(* Logix 5000 project; controller V16_L55_Blank vendor 1 type 14 code 51 rev 16.2; software revision 16.04 *)

TASK MainTask (continuous, watchdog 500 ms) : MainProgram

MODULES
   Local : vendor 1 type 14 code 51 (ICP 0, rev 16.2)
      MVI69E_AFC : vendor 1 type 0 code 15 (ICP 1, rev 1.1, Output RPI 5 ms)
END_MODULES

TYPE AFCEComponents :   // High precision gas component analysis (only supported version 2.07.000)
STRUCT
   C1 : REAL;   // Methane
   N2 : REAL;   // Nitrogen
   CO2 : REAL;   // Carbon Dioxide
   C2 : REAL;   // Ethane
   C3 : REAL;   // Propane
   H20 : REAL;   // Water
   H2S : REAL;   // Hydrogen Sulphide
   H2 : REAL;   // Hydrogen
   CO : REAL;   // Carbon Monoxide
   O2 : REAL;   // Oxygen
   IC4 : REAL;   // Iso-butane
   NC4 : REAL;   // Normal Butane
   IC5 : REAL;   // Iso-pentane
   NC5 : REAL;   // Normal-pentane
   C6 : REAL;   // Hexane
   C7 : REAL;   // Heptane
   C8 : REAL;   // Octane
   C9 : REAL;   // Nonane
   C10 : REAL;   // Decane
   He : REAL;   // Helium
   Ar : REAL;   // Argon
   NeoC5 : REAL;   // Not Used
   UxUser1 : REAL;   // Not Used
   UyUser2 : REAL;   // Not Used
   UxUser3 : REAL;   // Not Used
   UyUser4 : REAL;   // Not Used
   UxUser5 : REAL;   // Not Used
   UyUser6 : REAL;   // Not Used
   UxUser7 : REAL;   // Not Used
   UyUser8 : REAL;   // Not Used
   UxUser9 : REAL;   // Not Used
   UyUser10 : REAL;   // Not Used
END_STRUCT
END_TYPE

TYPE AFCEExtended :
STRUCT
   Trigger : BOOL;
   Data : AFCEExtendedData;
END_STRUCT
END_TYPE

TYPE AFCEExtendedData :
STRUCT
   Raw : INT[64];
END_STRUCT
END_TYPE

TYPE AFCEFirmwareVersion :
STRUCT
   Major : SINT;   // Major Version number
   Minor : SINT;   // Minor Version number
   Revision : INT;   // Revision
END_STRUCT
END_TYPE

TYPE AFCEFlag :   // Flags contains status information updated by ladder and also trigger bits for clock update
STRUCT
   AFCStopped : BOOL;   // Indicates that the module has sent a new input block to be processed by ladder - UPDATED BY LADDER
   AFCInputSequenceNum : INT;   // Meter number (0 -15) associated to blocks 1-16. Used to update "Profile" (meter type and product group.) UPDATED BY LADDER
END_STRUCT
END_TYPE

TYPE AFCEMeterAnalysis :   // Meter analysis components. Allows the processor to update molar analysis for low precision and high precision streams.
STRUCT
   Trigger : BOOL;   // Set to 1 to Send Updated Component Data to the Module
   Stream : INT;   // Stream for Analysis. Select 0 for current active stream.
   Error : AFCEMeterAnalysisError;   // Analysis Error
   Components : AFCEComponents;   // High precision gas components (floating point per component). Only supported for firmware version 2.07.000 or later
END_STRUCT
END_TYPE

TYPE AFCEMeterAnalysisError :
STRUCT
   StreamOutOfRange : BOOL;   // Requested Stream Number Out of Range
   StreamNotConfigured : BOOL;   // Requested Stream Not Configured
END_STRUCT
END_TYPE

TYPE AFCEMeterArchiveFetchError :
STRUCT
   ArchiveSelectionInvalid : BOOL;   // Archive File Selection Invalid
   AgeOutsideSize : BOOL;   // Age Outside Configured File Size
   ArchiveNeverWritten : BOOL;   // Age OK but Archive Record Never Written (new or reconfigured meter)
   Reserverd1 : BOOL;
   Reserverd2 : BOOL;
   Reserverd3 : BOOL;
   Reserverd4 : BOOL;
   Reserverd5 : BOOL;
   Reserverd6 : BOOL;
   Reserverd7 : BOOL;
   Reserverd8 : BOOL;
   Reserverd9 : BOOL;
   Reserverd10 : BOOL;
   Reserverd11 : BOOL;
   Reserverd12 : BOOL;
   Reserverd13 : BOOL;
END_STRUCT
END_TYPE

TYPE AFCEMeterCalRequestActionType :
STRUCT
   ZeroShift : BOOL;   // Zero Shift
   SetZero : BOOL;   // Set Zero
   SetSpan : BOOL;   // Set Span
   SetMid1 : BOOL;   // Set Mid 1
   SetMid2 : BOOL;   // Set Mid 2
   SetMid3 : BOOL;   // Set Mid 3
END_STRUCT
END_TYPE

TYPE AFCEMeterCalRequestActionValue :
STRUCT
   ZeroShift : AFCEMeterCalRequestValue;   // Zero Shift
   SetZero : AFCEMeterCalRequestValue;   // Set Zero
   SetSpan : AFCEMeterCalRequestValue;   // Set Span
   SetMid1 : AFCEMeterCalRequestValue;   // Set Mid 1
   SetMid2 : AFCEMeterCalRequestValue;   // Set Mid 2
   SetMid3 : AFCEMeterCalRequestValue;   // Set Mid 3
END_STRUCT
END_TYPE

TYPE AFCEMeterCalRequestValue :
STRUCT
   Applied : REAL;   // Applied
   Measured : REAL;   // Measured
END_STRUCT
END_TYPE

TYPE AFCEMeterCalResponse :
STRUCT
   Trigger : BOOL;   // Send Error Code and Values to module to be recorded
   ErrorCode : SINT;   // Error Code to send. 0-4 allowed. 0=No error. 1-4=User defined.
   Value : AFCEMeterCalRequestValue;   // Value to Send
   Count : DINT;   // Number of calibration responses
END_STRUCT
END_TYPE

TYPE AFCEMeterControl :   // Enable/Disable Meter and Streams
STRUCT
   Meter : AFCEMeterControlMeter;   // Control the Meter
   Stream : AFCEMeterControlStream;   // Control the Meter Streams
   ResetAccumulators : AFCEMeterSignals;   // Resets for meter accumulators
END_STRUCT
END_TYPE

TYPE AFCEMeterControlMeter :   // Enable and Disable Meter
STRUCT
   Enable : BOOL;   // Enable the Meter
   Disable : BOOL;   // Disable the Meter
END_STRUCT
END_TYPE

TYPE AFCEMeterControlStream :
STRUCT
   Selected : SINT;   // Stream to Enable or Disable and/or make active.
   EnableSelected : BOOL;   // Enable the Selected Stream
   DisableSelected : BOOL;   // Disable the Selected Stream
   SetSelectedToActive : BOOL;   // Set Selected to Active Stream
END_STRUCT
END_TYPE

TYPE AFCEMeterDifferentialGas :   // Differential Gas Meter
STRUCT
   Control : AFCEMeterControl;   // Meter Control
   Status : AFCEMeterStatus;   // Meter Status
   ProcessVariables : AFCEMeterDifferentialGasProcess;   // Input process variables to be transferred to the module
   Analysis : AFCEMeterAnalysis;   // Molar Analysis data to be transferred to the module (only for gas products with online gas chromatograph applications)
   Alarm : AFCEMeterDifferentialGasAlarm;   // Meter Alarm status and control
   Archive : AFCEMeterDifferentialGasArchive;   // Archive
   Profile : AFCEMeterProfile;   // Module profile (meter type/product group) transfered from the module
   Calibration : AFCEMeterDifferentialGasCal;   // Calibration
   BackPlaneReturn : AFCEMeterDifferentialGasBackPlaneReturn;
END_STRUCT
END_TYPE

TYPE AFCEMeterDifferentialGasAlarm :   // Alarm Status and Control
STRUCT
   Control : AFCEMeterDifferentialGasAlarmControl;   // Alarm Control
END_STRUCT
END_TYPE

TYPE AFCEMeterDifferentialGasAlarmControl :   // Differential Gas Process Alarm Control
STRUCT
   DifferentialPressure : AFCEMeterProcessAlarm;   // Differential Pressure Alarms
   FlowRate : AFCEMeterProcessAlarm;   // Flow Rate
   Temperature : AFCEMeterProcessAlarm;   // Temperature Alarms
   Pressure : AFCEMeterProcessAlarm;   // Pressure Alarms
END_STRUCT
END_TYPE

TYPE AFCEMeterDifferentialGasArchive :   // Different Gas Archive
STRUCT
   Write : AFCEMeterDifferentialGasArchiveWrite;
   Fetch : AFCEMeterDifferentialGasArchiveFetch;
END_STRUCT
END_TYPE

TYPE AFCEMeterDifferentialGasArchiveDflt :   // Default Configuration
STRUCT
   ClosingTimestamp : DINT;
   CumulativeActiveStreams : INT;
   CurrentActiveStream : SINT;
   MeterStatus : SINT;
   FlowingPeriod : DINT;
   PeriodDuration : DINT;
   AccumulatorTotalizer : DINT;
   AccumulatorResidue : REAL;
   MeterAlarms : DINT;
   PrimaryInput : REAL;   // Either Differential Pressure or Flow Rate
   Temperature : REAL;
   Pressure : REAL;
   RelativeDensity : REAL;
   ReferenceCompressibility : REAL;
   FlowingCompressibility : REAL;
   Fpv : REAL;
   PressureExtension : REAL;
   CoefficientDischarge : REAL;
   ExpansionFactor : REAL;
   Cprime : REAL;
   MassNRAccumulatorCurrent : REAL;   // Non-resettable
   MassNRAccumulatorOpening : REAL;   // Non-resettable
   EnergyNRAccumulatorCurrent : REAL;   // Non-resettable
   EnergyNRAccumulatorOpening : REAL;   // Non-resettable
   NetNRAccumulatorCurrent : REAL;   // Non-resettable
   NetNRAccumulatorOpening : REAL;   // Non-resettable
   GrossNRAccumulatorCurrent : REAL;   // Non-resettable
   GrossNRAccumulatorOpening : REAL;   // Non-resettable
   MolarFractionComponent01_C1 : REAL;
   MolarFractionComponent02_N2 : REAL;
   MolarFractionComponent03_CO2 : REAL;
   MolarFractionComponent04_C2 : REAL;
   MolarFractionComponent05_C3 : REAL;
   MolarFractionComponent06_H2O : REAL;
   MolarFractionComponent07_H2S : REAL;
   MolarFractionComponent08_H2 : REAL;
   MolarFractionComponent09_CO : REAL;
   MolarFractionComponent10_O2 : REAL;
   MolarFractionComponent11_IC4 : REAL;
   MolarFractionComponent12_NC4 : REAL;
   MolarFractionComponent13_IC5 : REAL;
   MolarFractionComponent14_NC5 : REAL;
   MolarFractionComponent15_C6 : REAL;
   MolarFractionComponent16_C7 : REAL;
   MolarFractionComponent17_C8 : REAL;
   MolarFractionComponent18_C9 : REAL;
   MolarFractionComponent19_C10 : REAL;
   MolarFractionComponent20_He : REAL;
   MolarFractionComponent21_Ar : REAL;
   UserDefinedFlowAverage1 : REAL;
   UserDefinedFlowAverage2 : REAL;
   UserDefinedFlowAverage3 : REAL;
END_STRUCT
END_TYPE

TYPE AFCEMeterDifferentialGasArchiveFetch :
STRUCT
   Daily : AFCEMeterDifferentialGasArchiveFetchT;
   Hourly : AFCEMeterDifferentialGasArchiveFetchT;
END_STRUCT
END_TYPE

TYPE AFCEMeterDifferentialGasArchiveFetchT :   // Fetch Archive
STRUCT
   Trigger : BOOL;   // Trigger Archive Fetch
   Age : INT;   // Initial Archive. 0 = Current Archive
   Error : AFCEMeterArchiveFetchError;   // Archive Fetch Error
   Default : AFCEMeterDifferentialGasArchiveDflt;   // Default Archive
   Raw : INT[100];   // Raw Archive
END_STRUCT
END_TYPE

TYPE AFCEMeterDifferentialGasArchiveWrite :   // Write Archive
STRUCT
   Daily : BOOL;   // Set to 1 to write daily archive
   Hourly : BOOL;   // Set to 1 to write hourly archive
END_STRUCT
END_TYPE

TYPE AFCEMeterDifferentialGasBackPlaneReturn :   // Differential Gas Meter
STRUCT
   StandardDefault : AFCEMeterDifferentialGasStandardDataDflt;
   StandardRaw : INT[14];
   Extended : AFCEExtended;
END_STRUCT
END_TYPE

TYPE AFCEMeterDifferentialGasCal :   // Processor Mediated Calibration
STRUCT
   Request : AFCEMeterDifferentialGasCalRequest;   // Calibration Request from module
   Response : AFCEMeterCalResponse;   // Processor Response
END_STRUCT
END_TYPE

TYPE AFCEMeterDifferentialGasCalRequest :
STRUCT
   ProcessVariable : AFCEMeterDifferentialGasCalRequestProces;   // Process Variable
   ActionType : AFCEMeterCalRequestActionType;   // Action Type
   Value : AFCEMeterCalRequestActionValue;   // Value
   Count : DINT;   // Number of calibration requests
END_STRUCT
END_TYPE

TYPE AFCEMeterDifferentialGasCalRequestProces :
STRUCT
   DifferentialPressure : BOOL;   // Differential Pressure
   Temperature : BOOL;   // Temperature
   Pressure : BOOL;   // Pressure
END_STRUCT
END_TYPE

TYPE AFCEMeterDifferentialGasProcess :   // Differential Gas Process Variables
STRUCT
   DifferentialPressure : REAL;   // Differential pressure if Primary Input = Differential pressure
   FlowRate : REAL;   // Flow Rate if Primary Input = Flow Rate
   Temperature : REAL;   // Temperature
   Pressure : REAL;   // Static pressure
END_STRUCT
END_TYPE

TYPE AFCEMeterDifferentialGasStandardDataDflt :   // EAFC Backplane Return Standard Data
STRUCT
   Meter_Alarms : DINT;   // Meter alarms
   NR_Acc_Net_Totalizer : DINT;   // Non-resettable accumulator, net, totalizer (m3)
   NR_Acc_Net_Residue : REAL;   // Non-resettable accumulator, net, residue (m3)
   FlowRate_Net : REAL;   // Flow rate, net (m3/h)
   FlowRate_Gross : REAL;   // Flow rate, gross (m3/h)
   Ifpv : REAL;   // AGA 8, Supercompressibility, Fpv
   Cprime : REAL;   // C-prime
END_STRUCT
END_TYPE

TYPE AFCEMeterDifferentialLiqBackPlaneReturn :   // Differential Liquid Meter
STRUCT
   StandardDefault : AFCEMeterDifferentialLiqStandardDataDflt;
   StandardRaw : INT[14];
   Extended : AFCEExtended;
END_STRUCT
END_TYPE

TYPE AFCEMeterDifferentialLiqCal :   // Processor Mediated Calibration
STRUCT
   Request : AFCEMeterDifferentialLiqCalRequest;   // Calibration Request from module
   Response : AFCEMeterCalResponse;   // Processor Response
END_STRUCT
END_TYPE

TYPE AFCEMeterDifferentialLiqCalRequest :
STRUCT
   ProcessVariable : AFCEMeterDifferentialLiqCalRequestProces;   // Process Variable
   ActionType : AFCEMeterCalRequestActionType;   // Action Type
   Value : AFCEMeterCalRequestActionValue;   // Value
   Count : DINT;   // Number of calibration requests
END_STRUCT
END_TYPE

TYPE AFCEMeterDifferentialLiqCalRequestProces :
STRUCT
   DifferentialPressure : BOOL;   // Differential Pressure
   Temperature : BOOL;   // Temperature
   Pressure : BOOL;   // Pressure
   Density : BOOL;   // Density
   WaterContent : BOOL;   // Water Content
END_STRUCT
END_TYPE

TYPE AFCEMeterDifferentialLiqStandardDataDflt :   // EAFC Backplane Return Standard Data
STRUCT
   Meter_Alarms : DINT;   // Meter alarms
   NR_Acc_Net_Totalizer : DINT;   // Non-resettable accumulator, net, totalizer (m3)
   NR_Acc_Net_Residue : REAL;   // Non-resettable accumulator, net, residue (m3)
   FlowRate_Net : REAL;   // Flow rate, net (m3/h)
   NR_Acc_Gross_Totalizer : DINT;   // Non-resettable accumulator, gross, totalizer (m3)
   NR_Acc_GrossStandard_Totalizer : DINT;   // Non-resettable accumulator, gross standard, totalizer (m3)
   NR_Acc_Mass_Totalizer : DINT;   // Non-resettable accumulator, mass, totalizer (kg)
END_STRUCT
END_TYPE

TYPE AFCEMeterDifferentialLiquid :   // Differential Liquid Meter
STRUCT
   Control : AFCEMeterControl;   // Meter Control
   Status : AFCEMeterStatus;   // Meter Status
   ProcessVariables : AFCEMeterDifferentialLiquidProcess;   // Input process variables to be transferred to the module
   Analysis : AFCEMeterAnalysis;   // Molar Analysis data to be transferred to the module (only for gas products with online gas chromatograph applications)
   Alarm : AFCEMeterDifferentialLiquidAlarm;   // Meter Alarms
   Archive : AFCEMeterDifferentialLiquidArchive;   // Archive
   Profile : AFCEMeterProfile;   // Module profile (meter type/product group) transfered from the module
   Calibration : AFCEMeterDifferentialLiqCal;   // Calibration
   BackPlaneReturn : AFCEMeterDifferentialLiqBackPlaneReturn;
END_STRUCT
END_TYPE

TYPE AFCEMeterDifferentialLiquidAlarm :
STRUCT
   Control : AFCEMeterDifferentialLiquidAlarmControl;   // Alarm Control
END_STRUCT
END_TYPE

TYPE AFCEMeterDifferentialLiquidAlarmControl :   // Differential Liquid Process Alarms
STRUCT
   DifferentialPressure : AFCEMeterProcessAlarm;   // Differential Pressure Alarms
   FlowRate : AFCEMeterProcessAlarm;   // Flow Rate
   Temperature : AFCEMeterProcessAlarm;   // Temperature Alarms
   Pressure : AFCEMeterProcessAlarm;   // Pressure Alarms
   Density : AFCEMeterProcessAlarm;   // Density Alarms
   WaterPercent : AFCEMeterProcessAlarm;   // Differential Pressure Alarms
END_STRUCT
END_TYPE

TYPE AFCEMeterDifferentialLiquidArchive :   // Different Liquid Archive
STRUCT
   Write : AFCEMeterDifferentialLiquidArchiveWrite;
   Fetch : AFCEMeterDifferentialLiquidArchiveFetch;
END_STRUCT
END_TYPE

TYPE AFCEMeterDifferentialLiquidArchiveDflt :   // Default Configuration
STRUCT
   ClosingTimestamp : DINT;
   CumulativeActiveStreams : INT;
   CurrentActiveStream : SINT;
   MeterStatus : SINT;
   FlowingPeriod : DINT;
   PeriodDuration : DINT;
   AccumulatorTotalizer : DINT;
   AccumulatorResidue : REAL;
   MeterAlarms : DINT;
   PrimaryInput : REAL;   // Either Differential Pressure or Flow Rate
   Temperature : REAL;
   Pressure : REAL;
   Density : REAL;
   WaterContent : REAL;
   ReferenceDensity : REAL;
   Ctpl : REAL;
   AGA3DensityExtension : REAL;
   AGA3CoefficientDischarge : REAL;
   Available01 : INT;
   Available02 : INT;
   Cprime : REAL;
   MassNRAccumulatorCurrent : REAL;   // Non-resettable
   MassNRAccumulatorOpening : REAL;   // Non-resettable
   Available03 : INT;
   Available04 : INT;
   Available05 : INT;
   Available06 : INT;
   NetNRAccumulatorCurrent : REAL;   // Non-resettable
   NetNRAccumulatorOpening : REAL;   // Non-resettable
   GrossNRAccumulatorCurrent : REAL;   // Non-resettable
   GrossNRAccumulatorOpening : REAL;   // Non-resettable
   GrossStandardNRAccumulatorOpening : REAL;   // Non-resettable
   GrossStandardNRAccumulatorCurrent : REAL;   // Non-resettable
   WaterNRAccumulatorCurrent : REAL;   // Non-resettable
   WaterNRAccumulatorOpening : REAL;   // Non-resettable
   API2540VaporPressureAbs : REAL;   // Non-resettable
   Available07 : INT;
   Available08 : INT;
   UserSpecifiedFlowAverage1 : REAL;
   UserSpecifiedFlowAverage2 : REAL;
   UserSpecifiedFlowAverage3 : REAL;
END_STRUCT
END_TYPE

TYPE AFCEMeterDifferentialLiquidArchiveFetch :
STRUCT
   Daily : AFCEMeterDifferentialLiquidArchiveFetchT;
   Hourly : AFCEMeterDifferentialLiquidArchiveFetchT;
END_STRUCT
END_TYPE

TYPE AFCEMeterDifferentialLiquidArchiveFetchT :   // Fetch Archive
STRUCT
   Trigger : BOOL;   // Trigger Archive Fetch
   Age : INT;   // 0 = Current Archive
   Error : AFCEMeterArchiveFetchError;   // Archive Fetch Error
   Default : AFCEMeterDifferentialLiquidArchiveDflt;   // Default Archive
   Raw : INT[100];   // Raw Archive
END_STRUCT
END_TYPE

TYPE AFCEMeterDifferentialLiquidArchiveWrite :   // Write Archive
STRUCT
   Daily : BOOL;   // Set to 1 to write daily archive
   Hourly : BOOL;   // Set to 1 to write hourly archive
END_STRUCT
END_TYPE

TYPE AFCEMeterDifferentialLiquidProcess :   // Differential Liquid Process Variables
STRUCT
   DifferentialPressure : REAL;   // Differential pressure if Primary Input = Differential pressure
   FlowRate : REAL;   // Flow Rate if Primary Input = Flow Rate
   Temperature : REAL;   // Temperature
   Pressure : REAL;   // Static Pressure
   Density : REAL;   // Density
   WaterPercent : REAL;   // Water %
END_STRUCT
END_TYPE

TYPE AFCEMeterLinearGas :   // Linear Gas Meter
STRUCT
   Control : AFCEMeterControl;   // Meter Control
   Status : AFCEMeterStatus;   // Meter Status
   ProcessVariables : AFCEMeterLinearGasProcess;   // Input process variables to be transferred to the module
   Analysis : AFCEMeterAnalysis;   // Molar Analysis data to be transferred to the module (only for gas products with online gas chromatograph applications)
   Alarm : AFCEMeterLinearGasAlarm;   // Meter Alarms
   Archive : AFCEMeterLinearGasArchive;   // Archive
   Profile : AFCEMeterProfile;   // Module profile (meter type/product group) transfered from the module
   Calibration : AFCEMeterLinearGasCal;   // Calibration
   BackPlaneReturn : AFCEMeterLinearGasBackPlaneReturn;
END_STRUCT
END_TYPE

TYPE AFCEMeterLinearGasAlarm :
STRUCT
   Control : AFCEMeterLinearGasAlarmControl;   // Alarm Control
END_STRUCT
END_TYPE

TYPE AFCEMeterLinearGasAlarmControl :   // Linear Gas Process Alarms
STRUCT
   PulseFrequency : AFCEMeterProcessAlarm;   // Pulse Frequency Alarms
   Temperature : AFCEMeterProcessAlarm;   // Temperature Alarms
   Pressure : AFCEMeterProcessAlarm;   // Pressure Alarms
   MeterPulses : AFCEMeterProcessAlarmFidelity;   // Meter Pulses Alarms
END_STRUCT
END_TYPE

TYPE AFCEMeterLinearGasArchive :   // Linear Gas Archive
STRUCT
   Write : AFCEMeterLinearGasArchiveWrite;
   Fetch : AFCEMeterLinearGasArchiveFetch;
END_STRUCT
END_TYPE

TYPE AFCEMeterLinearGasArchiveDflt :   // Default Configuration
STRUCT
   ClosingTimestamp : DINT;
   CumulativeActiveStreams : INT;
   CurrentActiveStream : SINT;
   MeterStatus : SINT;
   FlowingPeriod : DINT;
   PeriodDuration : DINT;
   AccumulatorTotalizer : DINT;
   AccumulatorResidue : REAL;
   MeterAlarms : DINT;
   PulseFrequency : REAL;
   Temperature : REAL;
   Pressure : REAL;
   RelativeDensity : REAL;
   ReferenceCompressibility : REAL;
   FlowingCompressibility : REAL;
   Fpv : REAL;
   KFactor : REAL;
   MeterFactor : REAL;
   InputPulseCount : DINT;
   CurrentManPulseCount : DINT;
   MassNRAccumulatorCurrent : REAL;   // Non-resettable
   MassNRAccumulatorOpening : REAL;   // Non-resettable
   EnergyNRAccumulatorCurrent : REAL;   // Non-resettable
   EnergyNRAccumulatorOpening : REAL;   // Non-resettable
   NetNRAccumulatorCurrent : REAL;   // Non-resettable
   NetNRAccumulatorOpening : REAL;   // Non-resettable
   GrossNRAccumulatorCurrent : REAL;   // Non-resettable
   GrossNRAccumulatorOpening : REAL;   // Non-resettable
   MolarFractionComponent01_C1 : REAL;
   MolarFractionComponent02_N2 : REAL;
   MolarFractionComponent03_CO2 : REAL;
   MolarFractionComponent04_C2 : REAL;
   MolarFractionComponent05_C3 : REAL;
   MolarFractionComponent06_H2O : REAL;
   MolarFractionComponent07_H2S : REAL;
   MolarFractionComponent08_H2 : REAL;
   MolarFractionComponent09_CO : REAL;
   MolarFractionComponent10_O2 : REAL;
   MolarFractionComponent11_IC4 : REAL;
   MolarFractionComponent12_NC4 : REAL;
   MolarFractionComponent13_IC5 : REAL;
   MolarFractionComponent14_NC5 : REAL;
   MolarFractionComponent15_C6 : REAL;
   MolarFractionComponent16_C7 : REAL;
   MolarFractionComponent17_C8 : REAL;
   MolarFractionComponent18_C9 : REAL;
   MolarFractionComponent19_C10 : REAL;
   MolarFractionComponent20_He : REAL;
   MolarFractionComponent21_Ar : REAL;
   UserSpecifiedFlowAverage1 : REAL;
   UserSpecifiedFlowAverage2 : REAL;
   UserSpecifiedFlowAverage3 : REAL;
END_STRUCT
END_TYPE

TYPE AFCEMeterLinearGasArchiveFetch :
STRUCT
   Daily : AFCEMeterLinearGasArchiveFetchT;
   Hourly : AFCEMeterLinearGasArchiveFetchT;
END_STRUCT
END_TYPE

TYPE AFCEMeterLinearGasArchiveFetchT :   // Fetch Archive
STRUCT
   Trigger : BOOL;   // Trigger Archive Fetch
   Age : INT;   // 0 = Current Archive
   Error : AFCEMeterArchiveFetchError;   // Archive Fetch Error
   Default : AFCEMeterLinearGasArchiveDflt;   // Default Archive
   Raw : INT[100];   // Raw Archive
END_STRUCT
END_TYPE

TYPE AFCEMeterLinearGasArchiveWrite :   // Write Archive
STRUCT
   Daily : BOOL;   // Set to 1 to write daily archive
   Hourly : BOOL;   // Set to 1 to write hourly archive
END_STRUCT
END_TYPE

TYPE AFCEMeterLinearGasBackPlaneReturn :   // Linear Gas Meter
STRUCT
   StandardDefault : AFCEMeterLinearGasStandardDataDflt;
   StandardRaw : INT[14];
   Extended : AFCEExtended;
END_STRUCT
END_TYPE

TYPE AFCEMeterLinearGasCal :   // Processor Mediated Calibration
STRUCT
   Request : AFCEMeterLinearGasCalRequest;   // Calibration Request from module
   Response : AFCEMeterCalResponse;   // Processor Response
END_STRUCT
END_TYPE

TYPE AFCEMeterLinearGasCalRequest :
STRUCT
   ProcessVariable : AFCEMeterLinearGasCalRequestProces;   // Process Variable
   ActionType : AFCEMeterCalRequestActionType;   // Action Type
   Value : AFCEMeterCalRequestActionValue;   // Value
   Count : DINT;   // Number of calibration requests
END_STRUCT
END_TYPE

TYPE AFCEMeterLinearGasCalRequestProces :
STRUCT
   PulseFrequency : BOOL;   // Pulse Frequency
   Temperature : BOOL;   // Temperature
   Pressure : BOOL;   // Pressure
END_STRUCT
END_TYPE

TYPE AFCEMeterLinearGasProcess :   // Linear Gas Process Variables
STRUCT
   PulseFrequency : REAL;   // Pulse Frequency (Hz)
   Temperature : REAL;   // Temperature
   Pressure : REAL;   // Pressure
   MeterPulses : DINT;   // Pulse count
END_STRUCT
END_TYPE

TYPE AFCEMeterLinearGasStandardDataDflt :   // EAFC Backplane Return Standard Data
STRUCT
   Meter_Alarms : DINT;   // Meter alarms
   NR_Acc_Net_Totalizer : DINT;   // Non-resettable accumulator, net, totalizer (m3)
   NR_Acc_Net_Residue : REAL;   // Non-resettable accumulator, net, residue (m3)
   FlowRate_Net : REAL;   // Flow rate, net (m3/h)
   FlowRate_Gross : REAL;   // Flow rate, gross / indicated (m3/h)
   Ifpv : REAL;   // AGA 8, Supercompressibility, Fpv
   Cprime : REAL;   // C-prime
END_STRUCT
END_TYPE

TYPE AFCEMeterLinearLiqBackPlaneReturn :   // Linear Liquid Meter
STRUCT
   StandardDefault : AFCEMeterLinearLiquidStandardDataDflt;
   StandardRaw : INT[14];
   Extended : AFCEExtended;
END_STRUCT
END_TYPE

TYPE AFCEMeterLinearLiquid :   // Linear Liquid Meter
STRUCT
   Control : AFCEMeterControl;   // Meter Control
   Status : AFCEMeterStatus;   // Meter Status
   ProcessVariables : AFCEMeterLinearLiquidProcess;   // Input process variables to be transferred to the module
   Analysis : AFCEMeterAnalysis;   // Molar Analysis data to be transferred to the module (only for gas products with online gas chromatograph applications)
   Alarm : AFCEMeterLinearLiquidAlarm;   // Meter Alarms
   Archive : AFCEMeterLinearLiquidArchive;   // Archive
   Profile : AFCEMeterProfile;   // Module profile (meter type/product group) transfered from the module
   Calibration : AFCEMeterLinearLiquidCal;   // Calibration
   BackPlaneReturn : AFCEMeterLinearLiqBackPlaneReturn;
END_STRUCT
END_TYPE

TYPE AFCEMeterLinearLiquidAlarm :
STRUCT
   Control : AFCEMeterLinearLiquidAlarmControl;   // Alarm Control
END_STRUCT
END_TYPE

TYPE AFCEMeterLinearLiquidAlarmControl :   // Linear Liquid Process Alarms
STRUCT
   PulseFrequency : AFCEMeterProcessAlarm;   // Pulse Frequency Alarms
   Temperature : AFCEMeterProcessAlarm;   // Temperature Alarms
   Pressure : AFCEMeterProcessAlarm;   // Pressure Alarms
   Density : AFCEMeterProcessAlarm;   // Density Alarms
   WaterPercent : AFCEMeterProcessAlarm;   // Water Percent Alarms
   MeterPulses : AFCEMeterProcessAlarmFidelity;   // Meter Pulses Alarms
END_STRUCT
END_TYPE

TYPE AFCEMeterLinearLiquidArchive :   // Different Liquid Archive
STRUCT
   Write : AFCEMeterLinearLiquidArchiveWrite;
   Fetch : AFCEMeterLinearLiquidArchiveFetch;
END_STRUCT
END_TYPE

TYPE AFCEMeterLinearLiquidArchiveDflt :   // Default Configuration
STRUCT
   ClosingTimestamp : DINT;   // Closing Timestamp
   CumulativeActiveStreams : INT;
   CurrentActiveStream : SINT;
   MeterStatus : SINT;
   FlowingPeriod : DINT;
   PeriodDuration : DINT;
   AccumulatorTotalizer : DINT;
   AccumulatorResidue : REAL;
   MeterAlarms : DINT;
   PulseFrequency : REAL;
   Temperature : REAL;
   Pressure : REAL;
   Density : REAL;
   WaterContent : REAL;
   ReferenceDensity : REAL;
   Ctpl : REAL;
   KFactor : REAL;
   MeterFactor : REAL;
   InputPulseCount : DINT;
   ManPulseCountCurrent : DINT;
   MassNRAccumulatorCurrent : REAL;   // Non-resettable
   MassNRAccumulatorOpening : REAL;   // Non-resettable
   Available01 : INT;
   Available02 : INT;
   Available03 : INT;
   Available04 : INT;
   NetNRAccumulatorCurrent : REAL;   // Non-resettable
   NetNRAccumulatorOpening : REAL;   // Non-resettable
   GrossNRAccumulatorCurrent : REAL;   // Non-resettable
   GrossNRAccumulatorOpening : REAL;   // Non-resettable
   GrossStandardNRAccumulatorOpening : REAL;   // Non-resettable
   GrossStandardNRAccumulatorCurrent : REAL;   // Non-resettable
   WaterNRAccumulatorCurrent : REAL;   // Non-resettable
   WaterNRAccumulatorOpening : REAL;   // Non-resettable
   API2540VaporPressureAbsolute : REAL;   // Non-resettable
   Available05 : INT;
   Available06 : INT;
   UserSpecifiedFlowAverage1 : REAL;
   UserSpecifiedFlowAverage2 : REAL;
   UserSpecifiedFlowAverage3 : REAL;
END_STRUCT
END_TYPE

TYPE AFCEMeterLinearLiquidArchiveFetch :
STRUCT
   Daily : AFCEMeterLinearLiquidArchiveFetchT;
   Hourly : AFCEMeterLinearLiquidArchiveFetchT;
END_STRUCT
END_TYPE

TYPE AFCEMeterLinearLiquidArchiveFetchT :   // Fetch Archive
STRUCT
   Trigger : BOOL;   // Trigger Archive Fetch
   Age : INT;   // 0 = Current Archive
   Error : AFCEMeterArchiveFetchError;   // Archive Fetch Error
   Default : AFCEMeterLinearLiquidArchiveDflt;   // Default Archive
   Raw : INT[100];   // Raw Archive
END_STRUCT
END_TYPE

TYPE AFCEMeterLinearLiquidArchiveWrite :   // Write Archive
STRUCT
   Daily : BOOL;   // Set to 1 to write daily archive
   Hourly : BOOL;   // Set to 1 to write hourly archive
END_STRUCT
END_TYPE

TYPE AFCEMeterLinearLiquidCal :   // Processor Mediated Calibration
STRUCT
   Request : AFCEMeterLinearLiquidCalRequest;   // Calibration Request from module
   Response : AFCEMeterCalResponse;   // Processor Response
END_STRUCT
END_TYPE

TYPE AFCEMeterLinearLiquidCalRequest :
STRUCT
   ProcessVariable : AFCEMeterLinearLiquidCalRequestProces;   // Process Variable
   ActionType : AFCEMeterCalRequestActionType;   // Action Type
   Value : AFCEMeterCalRequestActionValue;   // Value
   Count : DINT;   // Number of calibration requests
END_STRUCT
END_TYPE

TYPE AFCEMeterLinearLiquidCalRequestProces :
STRUCT
   PulseFrequency : BOOL;   // Pulse Frequency
   Temperature : BOOL;   // Temperature
   Pressure : BOOL;   // Pressure
   Density : BOOL;   // Density
   WaterContent : BOOL;   // Water Content
END_STRUCT
END_TYPE

TYPE AFCEMeterLinearLiquidProcess :   // Linear Liquid Process Variables
STRUCT
   PulseFrequency : REAL;   // Pulse frequency (Hz)
   Temperature : REAL;   // Temperature
   Pressure : REAL;   // Pressure
   Density : REAL;   // Density
   WaterPercent : REAL;   // Water (%)
   MeterPulses : DINT;   // Meter pulses
END_STRUCT
END_TYPE

TYPE AFCEMeterLinearLiquidStandardDataDflt :   // EAFC Backplane Return Standard Data
STRUCT
   Meter_Alarms : DINT;   // Meter alarms
   NR_Acc_Net_Totalizer : DINT;   // Non-resettable accumulator, net, totalizer (m3)
   NR_Acc_Net_Residue : REAL;   // Non-resettable accumulator, net, residue (m3)
   FlowRate_Net : REAL;   // Flow rate, net (m3/h)
   NR_Acc_Gross_Totalizer : DINT;   // Non-resettable accumulator, gross / indicated, totalizer (m3)
   NR_Acc_GrossStandard_Totalizer : DINT;   // Non-resettable accumulator, gross standard, totalizer (m3)
   NR_Acc_Mass_Totalizer : DINT;   // Non-resettable accumulator, mass, totalizer (kg)
END_STRUCT
END_TYPE

TYPE AFCEMeterProcessAlarm :   // Process Alarms
STRUCT
   SetGeneralFail : BOOL;   // Set to indicate General Failure of the Transmitter
   StaleData : BOOL;   // Clear to Indicate new process input data
   SetLowThreshold : BOOL;   // Set to indicate Lower Range Limit Exceeded
   SetHighThreshold : BOOL;   // Set to indicate Upper Range Limit Exceeded
   SetAutoClearStaleData : BOOL;   // Set to automatically clear stale data
END_STRUCT
END_TYPE

TYPE AFCEMeterProcessAlarmFidelity :   // Process Alarms
STRUCT
   SetGeneralFail : BOOL;   // Set to indicate General Failure of the Transmitter
   StaleData : BOOL;   // Clear to Indicate new process input data
   Reserved : BOOL;   // Reserved
   SetPulseFidelityAlarm : BOOL;   // Set to indicate Pulse Fidelity Alarm
   SetAutoClearStaleData : BOOL;   // Set to automatically clear stale data
END_STRUCT
END_TYPE

TYPE AFCEMeterProfile :   // Meter configuration profile
STRUCT
   MeterType : BOOL;   // 0=Differential, 1=Linear
   ProductGroup : BOOL;   // 0=Gas, 1=Liquid
   PrimaryInput : BOOL;   // For differential, 0=Differential Pressure 1=Flow Rate. For Linear, 0=Pulse Count 1=Pulse Frequency
   AOIMismatch : BOOL;   // AOI Meter type does not match module for meter number
END_STRUCT
END_TYPE

TYPE AFCEMeterSignals :   // Meter trigger accumulator and archive resets
STRUCT
   ResetAccumulator1 : BOOL;   // Set to 1 to reset resettable accumulator 1
   ResetAccumulator2 : BOOL;   // Set to 1 to reset resettable accumulator 2
   ResetAccumulator3 : BOOL;   // Set to 1 to reset resettable accumulator 3
   ResetAccumulator4 : BOOL;   // Set to 1 to reset resettable accumulator 4
END_STRUCT
END_TYPE

TYPE AFCEMeterStatus :   // Status
STRUCT
   Meter : AFCEMeterStatusMeter;   // Meter Status
   Stream : AFCEMeterStatusStream;   // Stream Status
END_STRUCT
END_TYPE

TYPE AFCEMeterStatusMeter :   // Meter Status
STRUCT
   Enabled : BOOL;   // Meter Enable Status, 1=enabled
   EnableAlarm : BOOL;   // If set either: 1. The meter is not configured. 2. The event log is full, the action was not performed.
END_STRUCT
END_TYPE

TYPE AFCEMeterStatusStream :
STRUCT
   Active : INT;   // Current Active Stream
   Enabled : AFCEMeterStatusStreamEnabled;   // Enabled Streams
   Configured : AFCEMeterStatusStreamEnabled;   // Configured Streams
   EnableAlarm : AFCEMeterStatusStreamAlarm;   // Enable Alarms
END_STRUCT
END_TYPE

TYPE AFCEMeterStatusStreamAlarm :   // Stream Alarms
STRUCT
   StreamOutOfRange : BOOL;   // Requested Stream Number Out of Range
   StreamNotConfigured : BOOL;   // Requested Stream not Configured
   StreamNotEnabled : BOOL;   // Requested Stream not Enabled
   EventLogFull : BOOL;   // Event Log Full, Action not Performed
END_STRUCT
END_TYPE

TYPE AFCEMeterStatusStreamEnabled :   // Stream Status 1 = Enabled
STRUCT
   Stream1 : BOOL;
   Stream2 : BOOL;
   Stream3 : BOOL;
   Stream4 : BOOL;
   Stream5 : BOOL;
   Stream6 : BOOL;
   Stream7 : BOOL;
   Stream8 : BOOL;
   Stream9 : BOOL;
   Stream10 : BOOL;
   Stream11 : BOOL;
   Stream12 : BOOL;
   Stream13 : BOOL;
   Stream14 : BOOL;
   Stream15 : BOOL;
   Stream16 : BOOL;
END_STRUCT
END_TYPE

TYPE AFCEModbusGateway :   // Modbus Gateway
STRUCT
   Command : AFCEModbusGatewayCommand[10];   // Modbus gateway commands - contains setup and modbus data
END_STRUCT
END_TYPE

TYPE AFCEModbusGatewayCommand :   // Modbus Gateway Command
STRUCT
   Config : AFCEModbusGatewayConfig;   // Config data to be entered by the user.
   Trigger : BOOL;   // Trigger the Command, when cleared module has responded.
   Data : INT[200];   // Contains modbus data written to the module (write commands)
END_STRUCT
END_TYPE

TYPE AFCEModbusGatewayConfig :   // Modbus Ggateway Configuration
STRUCT
   Enable : BOOL;   // Set to 1 to enable modbus gateway command (0=disable)
   StartRegister : DINT;   // Start modbus address
   RegisterCount : INT;   // Word count (200 max)
   FunctionType : BOOL;   // 0 = read command, 1 = write command
   RegisterType : BOOL;   // 0 = holding register, 1 = input register
   SlaveType : BOOL;   // 0 = primary slave, 1 = virtual slave
END_STRUCT
END_TYPE

TYPE AFCEModbusMaster :   // Modbus Master. Port 3 must be configured as modbus master through AFC Manager to use this feature.
STRUCT
   Enable : BOOL;   // Enable the modbus master funcionality
   CommandIndex : INT;   // Selects which command index will be executed
   Command : AFCEModbusMasterCommand[10];   // Each command contains a specific modbus request to be sent out of the port
END_STRUCT
END_TYPE

TYPE AFCEModbusMasterCommand :   // Modbus Master Command
STRUCT
   Config : AFCEModbusMasterConfig;   // Modbus Master Configuration
   ErrorCode : INT;   // Error Code associated to Modbus Master Command
   Pending : BOOL;   // Pending Modbus Master Command - waiting for Modbus Response
   ReturnedTransactionID : DINT;   // Changes to Config.TransactionID value when response has returned.
   Data : INT[100];   // Read or Write Data
END_STRUCT
END_TYPE

TYPE AFCEModbusMasterConfig :   // Modbus master command settings
STRUCT
   Enable : BOOL;   // Set to 1 to enable command (0=disable)
   FunctionType : BOOL;   // Set to 1 to select write command (0=read command)
   RegisterBank : BOOL;   // Set to 1 to select input register (0=holding register)
   DataType : AFCEModbusMasterDataType;   // Select data type format
   SwapOption : AFCEModbusMasterSwap;   // Select byte and word swap (1 = swap, 0 = no swap)
   TypeSwap : INT;   // This value is calculated by ladder logic and must not be modified by user
   SlaveAddress : INT;   // Modbus slave address of remote device
   ModbusAddress : INT;   // Modbus data address on remote slave
   ElementCount : INT;   // Number of data elements (125 words)
   TransactionID : INT;   // Transaction ID. This value is returned to the ReturnedTransaction ID when the response has been received.
END_STRUCT
END_TYPE

TYPE AFCEModbusMasterDataType :   // Modbus master data type
STRUCT
   Bit : BOOL;   // bit type
   Word : BOOL;   // word type (16-bit)
   Long : BOOL;   // long integer (32-bit)
   LongRemote : BOOL;   // long integer (32-bit)
END_STRUCT
END_TYPE

TYPE AFCEModbusMasterSwap :   // Modbus master swap words/ swap bytes
STRUCT
   SwapWords : BOOL;   // Swap words
   SwapBytes : BOOL;   // Swap bytes
END_STRUCT
END_TYPE

TYPE AFCEModbusPassThru :   // AFC Modbus Pass-thru
STRUCT
   Enable : BOOL;   // Set to 1 to enable pass-thru functionality (requires AFC Manager setting)
   MessagePresent : BOOL;   // Message present in the response block
   GetMessage : BOOL;   // Get the pass-thru message. When the bit is cleared the message has been transferred to the PLC.
   FunctionBitWrite : BOOL;   // Function bit write
   OverflowError : BOOL;   // Overflow error flag
   ModbusAddress : INT;   // Destination modbus address
   RegisterCount : INT;   // Number of elements associated to command
   ReadDataWord : INT[125];   // Contains received data for word commands
   ReadDataBit : AFCEModbusPassThruBitData;   // Contains received data for bit commands
END_STRUCT
END_TYPE

TYPE AFCEModbusPassThruBitData :   // AFC Modbus Pass-thru Bit Data
STRUCT
   Data : BOOL[2016];   // Contains received data for bit commands
END_STRUCT
END_TYPE

TYPE AFCEModuleDef :   // Main user defined data type
STRUCT
   ModbusGateway : AFCEModbusGateway;   // Reads and write data between processor and module modbus table
   ModbusMaster : AFCEModbusMaster;   // Setup modbus master commands to be sent to remote slaves (through Port 3)
   ModbusPassThru : AFCEModbusPassThru;   // Modbus pass-thru data
   SiteStatus : AFCESiteStatus;   // Site status
   MeterAlarms : AFCESiteAlarms;   // Meter Alarms
   Prove : AFCEProve;   // Prover
   Wallclock : AFCEWallclock;   // Set clock and get clock information
   Firmware : AFCEFirmwareVersion;   // Firmware information
   Util : AFCEUtil;   // Used by ladder logic
END_STRUCT
END_TYPE

TYPE AFCENetwork :
STRUCT
   Read : BOOL;   // Trigger to read network parameters
   Write : BOOL;   // Trigger to write network parameters
   Config : AFCENetworkConfig;   // Network parameters
   Error : INT;   // 0 = OK, -1 = Timeout, -2 = Gateway Index Out of Range
   Util : AFCENetworkUTIL;   // Internal variables
END_STRUCT
END_TYPE

TYPE AFCENetworkConfig :
STRUCT
   GatewayIndex : DINT;
   Physical_Interface_IP : INT[4];
   Physical_Interface_Network_Prefix : SINT;
   Default_Gateway_IP : INT[4];   // The IP address of the gateway. Must be in the same network as the web interface, or null.
   Server1_Network_Prefix : SINT;   // The network prefix length (number of subnet mask bits) of the interface for server 1; a number between 0 and 32.
   Server1_MBAP_Port : DINT;   // The Modbus-TCP port for server 1; 502, or a number between 1024 and 65535.
   Server1_Listener_IP : INT[4];   // The IP address of the network interface for server 1.
END_STRUCT
END_TYPE

TYPE AFCENetworkUTIL :
STRUCT
   State : INT;
   Buffer : SINT[240];
   TimeoutTimer : TIMER;
   TimeoutState : INT;
END_STRUCT
END_TYPE

TYPE AFCEProve :   // Prove
STRUCT
   Process : AFCEProveProcess;   // Process Variables
   Signals : AFCEProveSignals;   // AFC Prove Signals (triggers the proving update)
   Config : AFCEProveConfig;   // AFC Prove Control (configuration settings)
   PulseCounts : AFCEProvePulseCount;   // Pulse counts to be updated at the end of the run/pass
   ConfigInput : AFCEProveInputConfig;   // AFC prover input configuration
   Status : AFCEProveStatus;   // AFC prover status
   ErrorCode : INT;   // Prove error code
   ProveControlsEcho : INT;   // AFC module Echos the state of the Prove Controls
   RequestedMeterEcho : INT;   // AFC module Echos the Meter number requested
   RequestedCurvePointEcho : INT;   // AFC module Echos the requested Curve Point
   RunResults : AFCEProveRunResults;   // Prove and run results
   ProveEnabled : BOOL;   // ON if prove is enabled. This flag is coped from inputbuffer[247]
END_STRUCT
END_TYPE

TYPE AFCEProveConfig :   // Controls (configuration settings) associated to the prover
STRUCT
   Enable : AFCEProveConfigEnable;   // Controls at enable
   Accept : AFCEProveConfigAccept;   // Controls at accept
END_STRUCT
END_TYPE

TYPE AFCEProveConfigAccept :   // Prove controls at accept. If auto-accept is selected must be available at enable
STRUCT
   RequestedInterpolationPoint : INT;   // Requested interpolation point (0 nearest)
   ApplyMFChangeAllStreams : BOOL;   // Apply change in meter factor to all streams
   ApplyMFChangeCurve : BOOL;   // Apply change in meter factor to all curve points
   ApplyNewMF : BOOL;   // CApply new meter factor
END_STRUCT
END_TYPE

TYPE AFCEProveConfigEnable :   // Prove controls at enable
STRUCT
   MeterNumber : INT;   // Meter number requested (1-16)
   AutoAcceptProve : BOOL;   // Auto-accept the prove
   AutoContinueProve : BOOL;   // Auto-continue the prove
END_STRUCT
END_TYPE

TYPE AFCEProveInputConfig :   // Prove input block results - prover configuration
STRUCT
   Type : INT;   // Prover type
   Options : INT;   // Prover options
   RunsPerProveTotal : INT;   // Total runs per prove
   RunsPerProveSelected : INT;   // Selected runs per prove
   MaxRunsBeforeAbort : INT;   // Max total runs before abort
   ShortPassesPerRun : INT;   // Short passes per run if bidir = 2 , else 0
END_STRUCT
END_TYPE

TYPE AFCEProvePhaseBitmap :   // AFC prove phase bitmap
STRUCT
   NotSelected : BOOL;   // Not selected
   Active : BOOL;   // Active, not counting
   CountingPast1stSwitch : BOOL;   // Counting past 1st switch for Udir and forward leg for Bdir)
   Past2ndSwitchFwdLeg : BOOL;   // Past 2nd switch forward leg (bidirectional only)
   Past1stSwithRetLeg : BOOL;   // Past 1st switch return leg (bidirectional only)
   RunComplete : BOOL;   // Run complete. past 2nd switch.
END_STRUCT
END_TYPE

TYPE AFCEProveProcess :   // Prove process output from processor to the module
STRUCT
   Sequencing : AFCEProveSequencing;   // Prover sequencing
   Temperature : REAL;   // Temperature for Single Probe provers. And Inlet Temperature for Dual Probe Provers.
   OutletTemperature : REAL;   // Outlet Temperature for Provers with Dual Probes.
   SwitchBarTemperature : REAL;   // Switch bar temperature
   Pressure : REAL;   // Pressure for Single Probe provers. And Inlet Pressure for Dual Probe Provers.
   OutletPressure : REAL;   // Outlet Pressure for Provers with Dual Probes.
   ProverDensity : REAL;   // Prover density
END_STRUCT
END_TYPE

TYPE AFCEProvePulseCount :   // Values to be supplied at the end of the pass/run
STRUCT
   Meter : DINT;   // Meter pulse count
   MasterMeter : DINT;   // Master meter pulse count
END_STRUCT
END_TYPE

TYPE AFCEProveRunResults :   // Run results of the prove. Copied from the module to the pocessor
STRUCT
   CountAttempted : INT;   // Run count attempted
   CountCompleted : INT;   // Run count completed
   CountSelected : INT;   // Run count selected
   RunsSelected : INT;   // Bit Mapped Runs selected for calculations from completed runs
   NewMeterFactor : REAL;   // New meter factor
   ChangeInMeterFactor : REAL;   // Change in meter factor
END_STRUCT
END_TYPE

TYPE AFCEProveSequencing :   // AFC prove sequencing tag for phase selection and ball positioning
STRUCT
   Phase : AFCEProvePhaseBitmap;   // AFC phase sequencing
   BallPositionReady : BOOL;   // Ball position: Ready (Udir & Bdir only; fwd leg Bdir)
   BallPositionSealed : BOOL;   // Ball position: Sealed (Udir & Bdir only; fwd leg Bdir)
   BallPositionReadyBwdLeg : BOOL;   // Ball position: Ready bwd leg (Bdir only)
   BallPositionSealedBwdLeg : BOOL;   // Ball position: Sealed bwd leg (Bdir only)
END_STRUCT
END_TYPE

TYPE AFCEProveSignals :   // Contains the proving signals that will trigger specific tasks from the module
STRUCT
   EnableProve : BOOL;   // Enables the prove
   AcceptProve : BOOL;   // Accepts the prove
   RejectProve : BOOL;   // Reject the prove
   RunStart : BOOL;   // Starts the run
   RunComplete : BOOL;   // Flags that the run is complete
   RunCancel : BOOL;   // Cancels the run
   RunDelete : BOOL;   // Deletes the run
   PassComplete : BOOL;   // Flag that the pass is complete
   PauseProve : BOOL;   // Pauses the Proving Process
   AbortProve : BOOL;   // Aborts the prove
END_STRUCT
END_TYPE

TYPE AFCEProveStatus :   // Status of the prove (returned from the module to the processor)
STRUCT
   ProveAccepted : BOOL;   // Prove was accepted
   MeterFactorApplied : BOOL;   // Meter factor was applied
   MFAppliedToCurve : BOOL;   // Meter factor was applied to all points in the curve
   MFAppliedToStreams : BOOL;   // Meter factor was applied to all streams
   ProveRejectedByCommand : BOOL;   // Prove was rejected by command
   ProveRejectedNoRuns : BOOL;   // Prove was rejected - empty prove (no runs)
   ProveRejectedDivideBy0 : BOOL;   // Prove was rejected - divide by 0
   ProveEnabled : BOOL;   // Prove is enabled
   ProvingRunInProgress : BOOL;   // Proving run is in progress
   ProveRejectedAbort : BOOL;   // Prove rejected: abort
   ProvePaused : BOOL;   // Prove is paused
   RunCancelled : BOOL;   // Run Is cancelled
   RunTimedOut : BOOL;   // Run timed out
END_STRUCT
END_TYPE

TYPE AFCESiteAlarms :   // Indicates if a meter has any alarms
STRUCT
   Meter1 : BOOL;   // Meter in alarm
   Meter2 : BOOL;   // Meter in alarm
   Meter3 : BOOL;   // Meter in alarm
   Meter4 : BOOL;   // Meter in alarm
   Meter5 : BOOL;   // Meter in alarm
   Meter6 : BOOL;   // Meter in alarm
   Meter7 : BOOL;   // Meter in alarm
   Meter8 : BOOL;   // Meter in alarm
   Meter9 : BOOL;   // Meter in alarm
   Meter10 : BOOL;   // Meter in alarm
   Meter11 : BOOL;   // Meter in alarm
   Meter12 : BOOL;   // Meter in alarm
   Meter13 : BOOL;   // Meter in alarm
   Meter14 : BOOL;   // Meter in alarm
   Meter15 : BOOL;   // Meter in alarm
   Meter16 : BOOL;   // Meter in alarm
END_STRUCT
END_TYPE

TYPE AFCESiteStatus :   // Site status bits - contains general information about the module - not meter specific
STRUCT
   AFCActive : BOOL;   // AFC active
   ChecksumAlarms : BOOL;   // Checkum alarm active
   Reserved2 : BOOL;
   Reserved3 : BOOL;
   PLCHalted : BOOL;   // PLC in program mode or missing
   CfgChanged : BOOL;   // Configuration changed
   Powerup : BOOL;   // Module powered up
   ColdStart : BOOL;   // Module performed cold start (BBRAM initialized)
   ModbusMasterPending : BOOL;   // Modbus Master Poll Pending
   ModbusMasterComplete : BOOL;   // Modbus Master Poll Complete
   ModbusPassThruPending : BOOL;   // Modbus Pass-thru Input Pending
   CalibrationRequest : BOOL;   // Calibration request from module
   ProverEnabled : BOOL;   // Prover Enabled
   Reserved13 : BOOL;
   Reserved14 : BOOL;
   Reserved15 : BOOL;
END_STRUCT
END_TYPE

TYPE AFCETime :   // AFC time format used for wallclock update.
STRUCT
   Year : DINT;   // Year
   Month : DINT;   // Month
   Day : DINT;   // Day
   Hour : DINT;   // Hour
   Minute : DINT;   // Minute
   second : DINT;   // Seconds
END_STRUCT
END_TYPE

TYPE AFCEUtil :   // Used for internal ladder logic usage. These values must not be changed by user application.
STRUCT
   Flags : AFCEFlag;   // Wallclock update commands
   CycleCounter : INT;   // Reflects current block ID calculated by ladder to be sent to the module
   Buffer : AFCEUtilBuffer;
   Block : AFCEUtilBlock;
END_STRUCT
END_TYPE

TYPE AFCEUtilBlock :
STRUCT
   ProcessInput : INT;
   InterruptPending : AFCEUtilBlockInterrupt;
   InterruptComplete : AFCEUtilBlockInterrupt;
   NonInterruptPending : AFCEUtilBlockNonInterrupt;
   NonInterruptComplete : AFCEUtilBlockNonInterrupt;
END_STRUCT
END_TYPE

TYPE AFCEUtilBlockInterrupt :
STRUCT
   Now : BOOL;
   ModbusGateway : DINT;
   EnableDisable : BOOL;
   Analysis : DINT;
END_STRUCT
END_TYPE

TYPE AFCEUtilBlockNonInterrupt :
STRUCT
   Now : BOOL;
   ModbusMasterCommand : BOOL;
   ModbusMasterResponse : BOOL;
   Archive : DINT;
   Prover : BOOL;
   PassThru : BOOL;
   Calibration : BOOL;
END_STRUCT
END_TYPE

TYPE AFCEUtilBuffer :   // Buffer
STRUCT
   Input : INT[248];   // Input buffer contains the complete block to be copied from the module
   Output : INT[247];   // Output buffer contains data the complete block to be copied to the module
   Process : INT[180];
   ArchiveDay : INT[98];
   ArchiveHour : INT[98];
   Prove : INT[26];
   Analysis : INT[198];
   MeterEnableDisable : INT[4];
   StreamEnable : INT[36];
   StreamDisable : INT[36];
   StreamSelect : INT[24];
   MeterSignals : INT[24];
   Calibration : INT[36];
END_STRUCT
END_TYPE

TYPE AFCEWallclock :
STRUCT
   GetAFCTime : BOOL;   // Get current AFC Time
   SetAFCTimeFromPLCTime : BOOL;   // Set AFC time from PLC time. Updates current AFC time
   EnableLocalDateTime : BOOL;   // Enable Local Date Time.
   AFCTime : AFCETime;   // Coordinated Universal Time. Updated by either getting or setting AFC time.
END_STRUCT
END_TYPE

ADD_ON_INSTRUCTION AOI69EAFC   (* revision 1.5, ExecutePrescan *)
// Add-On instruction for the MVI69E-AFC.
// Module Interface.
// Revision note:
// Made changes to the ModbusGatewayConfig UDT StartRegister Tag Data Type from INT to DINT.
// Help:
// Compatible with version 4.04 of MVI69E-AFC firmware or higher.
// v1.3: Option to choose LocalDateTime.
// v1.4: Changed Prescan FLL instruction length from 240 words to 180 for proccess inputs. This stopped mismatch issue
// v1.4: Changed COP instruction length from 240 words to 180 on rung 19 for procces inputs to output block. Modified ProfileBlockID INT to DINT.
// v1.5: Made changes to the ModbusGatewayConfig UDT StartRegister Tag Data Type from INT to DINT.
VAR_IN_OUT
   ConnectionInput : INT[248]; {required}
   ConnectionOutput : INT[247]; {required}
   AFC : AFCEModuleDef; {required}
        .UTIL.BUFFER.PROVE[12]   // Main user defined data type Buffer
END_VAR
VAR
   WallclockCurrentPLCTime : DINT[7];
   UTCTimeDelta : DINT;
   TimeZoneString : STRING;
   StoppedTimer : TIMER;
   ProverSignals : DINT;
   ProverPhase : DINT;
   ProverControls : DINT;
   ProveEnabled : BOOL;
   ProfileBlockID : DINT;
   ModbusMasterOutput : INT;
   CycleCounterPreviousStopped : INT;
   Offset1 : DINT;
   NotStoppedTimer : TIMER;
   ModbusPassThruOverflowError : BOOL;
   ModbusPassThruOutput : DINT;
   ModbusPassThruMessagePresent : BOOL;
   ModbusPassThruFunctionBitWrite : BOOL;
   ModbusMasterTransactionNumber : DINT;
   ModbusMasterReadWrite : BOOL;   // 0=Read 1=Write
   ModbusMasterPending : BOOL;
   ModbusMasterLongCount : DINT;
   ModbusGatewayReadWrite : BOOL;   // 0=Read, 1=Write
   ModbusGatewayOutput : DINT;
   ModbusGatewayIndexBitPosition : DINT;
   ModbusGatewayIndex : DINT;
   MJFAULTS : DINT[12];
   LocalHourChange : DINT;
   LatchStopped : BOOL;
   ForceReset : BOOL;
   AvoidBufferOverflowFault : DINT;   // Need this to prevent Overflow Minor Fault
   AFCTime : AFCETime;
END_VAR

ROUTINE Logic   (* ladder *)
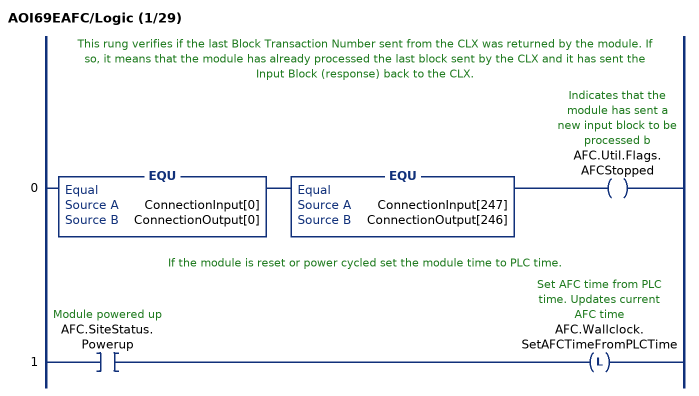
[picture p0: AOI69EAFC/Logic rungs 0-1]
   // This rung verifies if the last Block Transaction Number sent from the CLX was returned by the module. If so, it means that the module has already processed the last block sent by the CLX and it has sent the Input Block (response) back to the CLX.
   0: EQU(ConnectionInput[0],ConnectionOutput[0])EQU(ConnectionInput[247],ConnectionOutput[246])OTE(AFC.Util.Flags.AFCStopped);
   // If the module is reset or power cycled set the module time to PLC time.
   1: XIC(AFC.SiteStatus.Powerup)OTL(AFC.Wallclock.SetAFCTimeFromPLCTime);
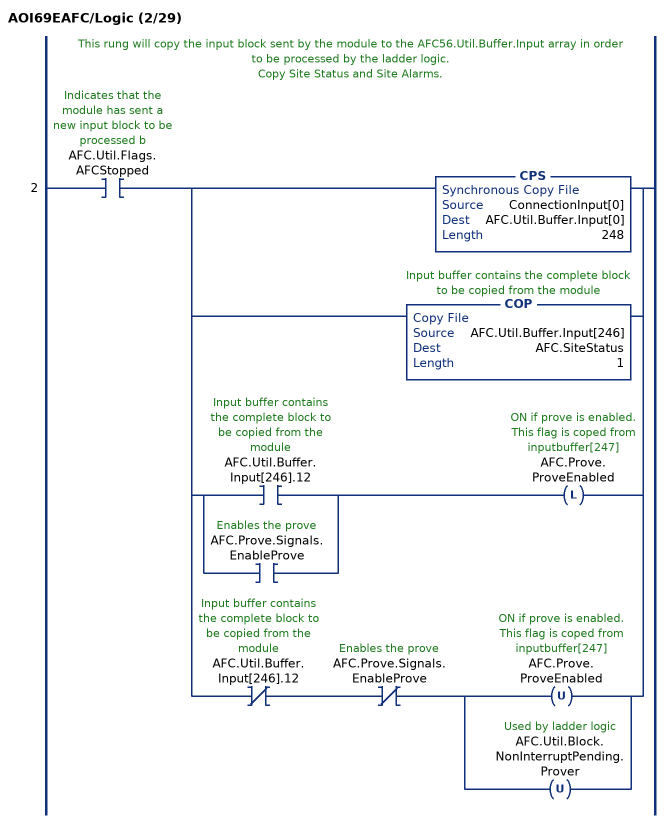
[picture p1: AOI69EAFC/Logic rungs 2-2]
   // This rung will copy the input block sent by the module to the AFC56.Util.Buffer.Input array in order to be processed by the ladder logic.
   // Copy Site Status and Site Alarms.
   2: XIC(AFC.Util.Flags.AFCStopped)[CPS(ConnectionInput[0],AFC.Util.Buffer.Input[0],248) ,COP(AFC.Util.Buffer.Input[246],AFC.SiteStatus,1) ,[XIC(AFC.Util.Buffer.Input[246].12) ,XIC(AFC.Prove.Signals.EnableProve) ] OTL(AFC.Prove.ProveEnabled) ,XIO(AFC.Util.Buffer.Input[246].12) XIO(AFC.Prove.Signals.EnableProve) [OTU(AFC.Prove.ProveEnabled) ,OTU(AFC.Util.Block.NonInterruptPending.Prover) ] ];
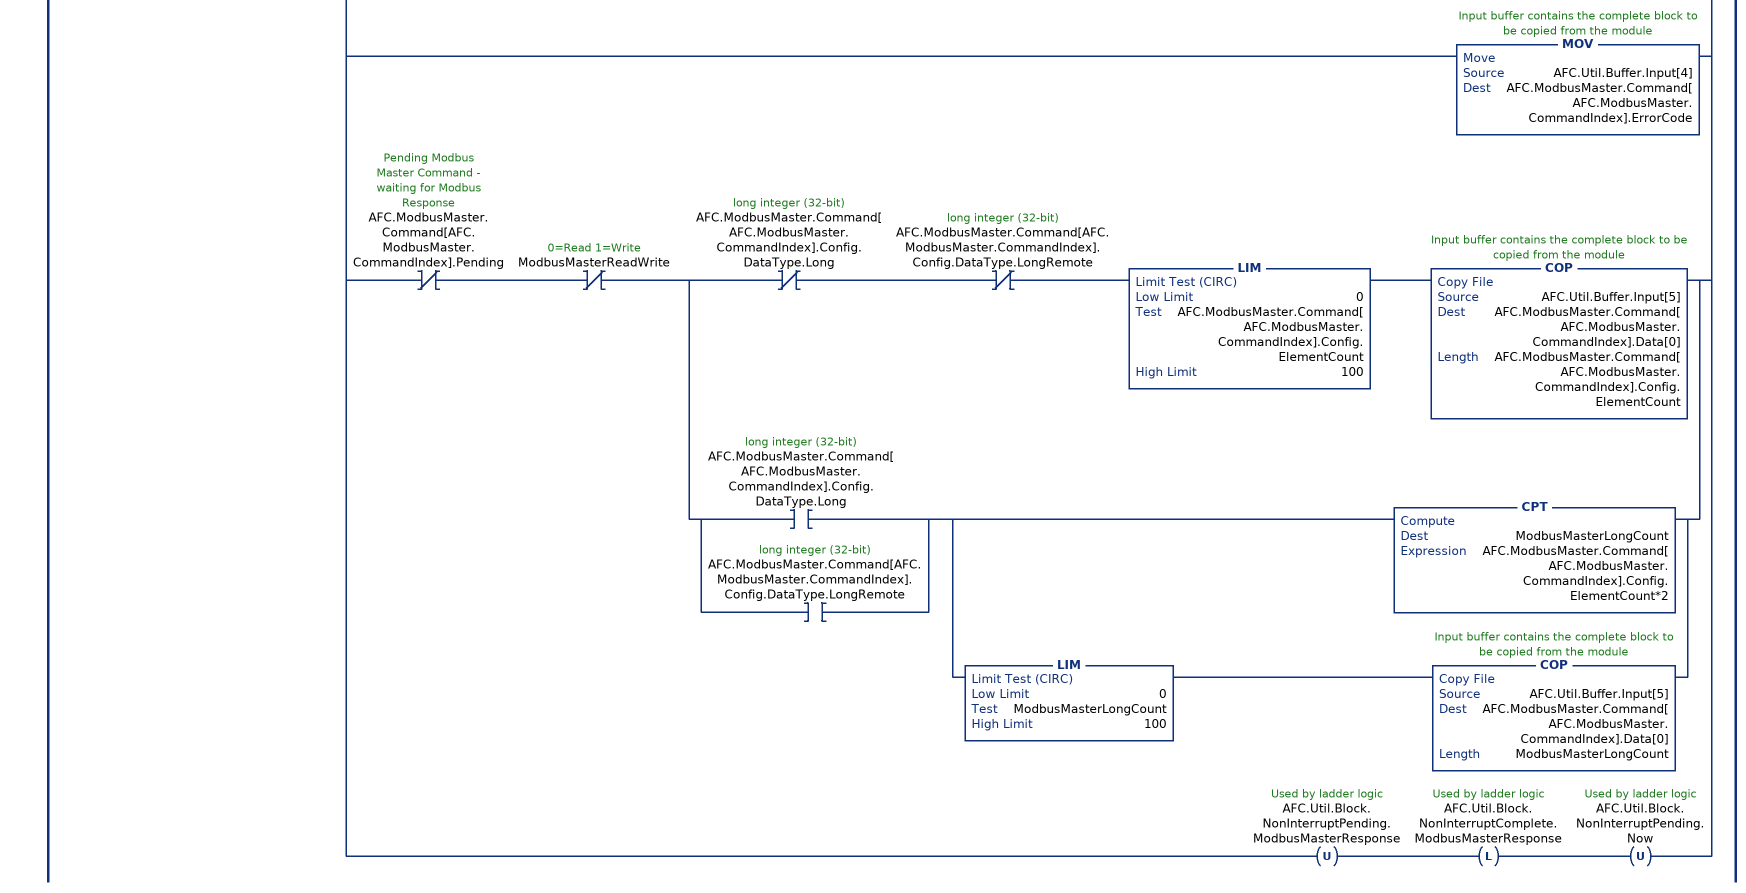
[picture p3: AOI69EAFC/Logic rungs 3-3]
   // Get Modbus Master data.
   3: XIC(AFC.Util.Flags.AFCStopped)XIC(AFC.ModbusMaster.Enable)LIM(0,AFC.ModbusMaster.CommandIndex,9)[EQU(AFC.Util.Buffer.Input[0],1000) [XIC(AFC.SiteStatus.ModbusMasterPending) OTL(AFC.ModbusMaster.Command[AFC.ModbusMaster.CommandIndex].Pending) ,XIO(AFC.SiteStatus.ModbusMasterPending) OTU(AFC.ModbusMaster.Command[AFC.ModbusMaster.CommandIndex].Pending) ,OTU(AFC.Util.Block.NonInterruptPending.ModbusMasterCommand) OTL(AFC.Util.Block.NonInterruptComplete.ModbusMasterCommand) OTU(AFC.Util.Block.NonInterruptPending.Now) ] ,EQU(AFC.Util.Buffer.Input[0],1001) [XIO(AFC.SiteStatus.ModbusMasterPending) OTU(AFC.ModbusMaster.Command[AFC.ModbusMaster.CommandIndex].Pending) ,MOV(AFC.Util.Buffer.Input[3],AFC.ModbusMaster.Command[AFC.ModbusMaster.CommandIndex].ReturnedTransactionID) ,MOV(AFC.Util.Buffer.Input[4],AFC.ModbusMaster.Command[AFC.ModbusMaster.CommandIndex].ErrorCode) ,XIO(AFC.ModbusMaster.Command[AFC.ModbusMaster.CommandIndex].Pending) XIO(ModbusMasterReadWrite) [XIO(AFC.ModbusMaster.Command[AFC.ModbusMaster.CommandIndex].Config.DataType.Long) XIO(AFC.ModbusMaster.Command[AFC.ModbusMaster.CommandIndex].Config.DataType.LongRemote) LIM(0,AFC.ModbusMaster.Command[AFC.ModbusMaster.CommandIndex].Config.ElementCount,100) COP(AFC.Util.Buffer.Input[5],AFC.ModbusMaster.Command[AFC.ModbusMaster.CommandIndex].Data[0],AFC.ModbusMaster.Command[AFC.ModbusMaster.CommandIndex].Config.ElementCount) ,[XIC(AFC.ModbusMaster.Command[AFC.ModbusMaster.CommandIndex].Config.DataType.Long) ,XIC(AFC.ModbusMaster.Command[AFC.ModbusMaster.CommandIndex].Config.DataType.LongRemote) ] [CPT(ModbusMasterLongCount,AFC.ModbusMaster.Command[AFC.ModbusMaster.CommandIndex].Config.ElementCount*2) ,LIM(0,ModbusMasterLongCount,100) COP(AFC.Util.Buffer.Input[5],AFC.ModbusMaster.Command[AFC.ModbusMaster.CommandIndex].Data[0],ModbusMasterLongCount) ] ] ,OTU(AFC.Util.Block.NonInterruptPending.ModbusMasterResponse) OTL(AFC.Util.Block.NonInterruptComplete.ModbusMasterResponse) OTU(AFC.Util.Block.NonInterruptPending.Now) ] ];
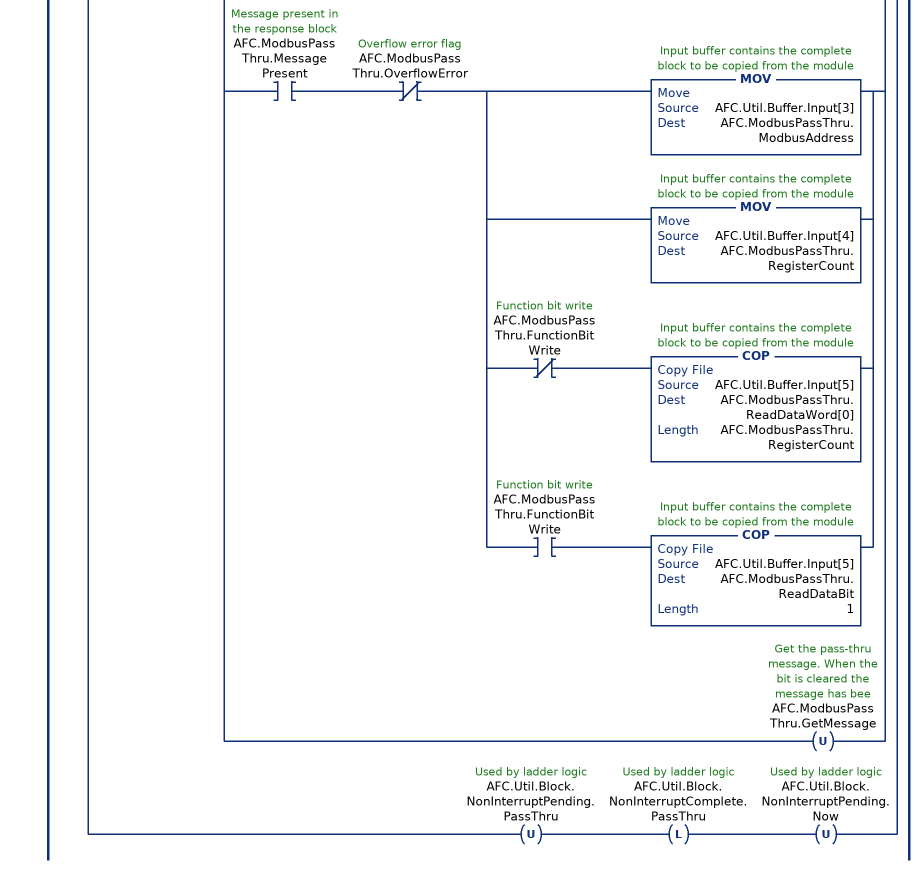
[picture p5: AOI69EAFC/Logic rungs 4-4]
   // Get Modbus Pass Thru data.
   4: XIC(AFC.Util.Flags.AFCStopped)EQU(AFC.Util.Buffer.Input[0],2000)XIC(AFC.ModbusPassThru.Enable)[XIC(AFC.ModbusPassThru.GetMessage) [[XIC(AFC.Util.Buffer.Input[2].0) OTL(AFC.ModbusPassThru.MessagePresent) ,XIO(AFC.Util.Buffer.Input[2].0) OTU(AFC.ModbusPassThru.MessagePresent) ,XIC(AFC.Util.Buffer.Input[2].1) OTL(AFC.ModbusPassThru.FunctionBitWrite) ,XIO(AFC.Util.Buffer.Input[2].1) OTU(AFC.ModbusPassThru.FunctionBitWrite) ,XIC(AFC.Util.Buffer.Input[3].2) OTL(AFC.ModbusPassThru.OverflowError) ,XIO(AFC.Util.Buffer.Input[3].2) OTU(AFC.ModbusPassThru.OverflowError) ] ,XIC(AFC.ModbusPassThru.MessagePresent) XIO(AFC.ModbusPassThru.OverflowError) [MOV(AFC.Util.Buffer.Input[3],AFC.ModbusPassThru.ModbusAddress) ,MOV(AFC.Util.Buffer.Input[4],AFC.ModbusPassThru.RegisterCount) ,XIO(AFC.ModbusPassThru.FunctionBitWrite) COP(AFC.Util.Buffer.Input[5],AFC.ModbusPassThru.ReadDataWord[0],AFC.ModbusPassThru.RegisterCount) ,XIC(AFC.ModbusPassThru.FunctionBitWrite) COP(AFC.Util.Buffer.Input[5],AFC.ModbusPassThru.ReadDataBit,1) ] ,OTU(AFC.ModbusPassThru.GetMessage) ] ,OTU(AFC.Util.Block.NonInterruptPending.PassThru) OTL(AFC.Util.Block.NonInterruptComplete.PassThru) OTU(AFC.Util.Block.NonInterruptPending.Now) ];
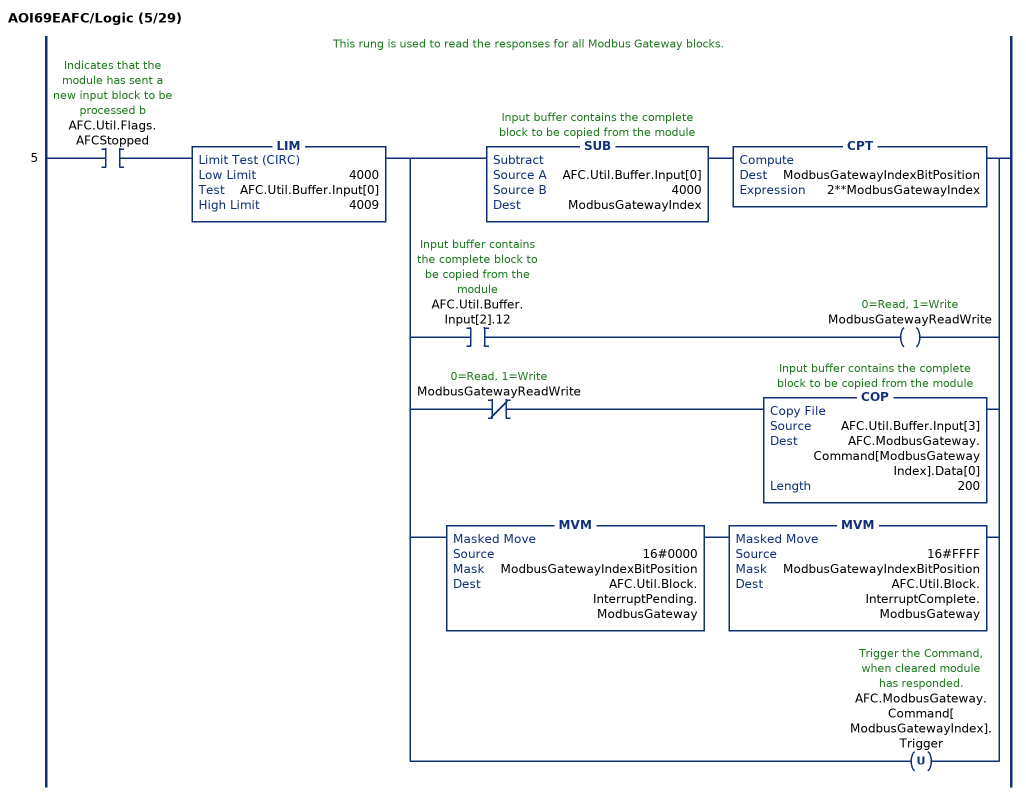
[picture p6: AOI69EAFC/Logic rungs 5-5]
   // This rung is used to read the responses for all Modbus Gateway blocks.
   5: XIC(AFC.Util.Flags.AFCStopped)LIM(4000,AFC.Util.Buffer.Input[0],4009)[SUB(AFC.Util.Buffer.Input[0],4000,ModbusGatewayIndex) CPT(ModbusGatewayIndexBitPosition,2**ModbusGatewayIndex) ,XIC(AFC.Util.Buffer.Input[2].12) OTE(ModbusGatewayReadWrite) ,XIO(ModbusGatewayReadWrite) COP(AFC.Util.Buffer.Input[3],AFC.ModbusGateway.Command[ModbusGatewayIndex].Data[0],200) ,MVM(16#0000,ModbusGatewayIndexBitPosition,AFC.Util.Block.InterruptPending.ModbusGateway) MVM(16#FFFF,ModbusGatewayIndexBitPosition,AFC.Util.Block.InterruptComplete.ModbusGateway) ,OTU(AFC.ModbusGateway.Command[ModbusGatewayIndex].Trigger) ];
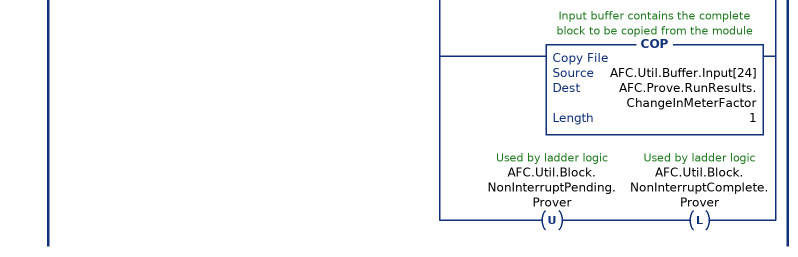
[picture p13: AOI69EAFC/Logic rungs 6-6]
   6: XIC(AFC.Util.Flags.AFCStopped)EQU(AFC.Util.Buffer.Input[0],5000)[XIC(ProverSignals.1) OTU(AFC.Prove.Signals.EnableProve) ,XIC(ProverSignals.2) OTU(AFC.Prove.Signals.AcceptProve) ,XIC(ProverSignals.3) OTU(AFC.Prove.Signals.RejectProve) ,XIC(ProverSignals.4) OTU(AFC.Prove.Signals.RunStart) ,XIC(ProverSignals.5) OTU(AFC.Prove.Signals.RunComplete) ,XIC(ProverSignals.6) OTU(AFC.Prove.Signals.RunCancel) ,XIC(ProverSignals.7) OTU(AFC.Prove.Signals.RunDelete) ,XIC(ProverSignals.9) OTU(AFC.Prove.Signals.PassComplete) ,XIC(ProverSignals.12) OTU(AFC.Prove.Signals.PauseProve) ,XIC(ProverSignals.14) OTU(AFC.Prove.Signals.AbortProve) ,MOV(AFC.Util.Buffer.Input[3],AFC.Prove.ConfigInput.Type) ,MOV(AFC.Util.Buffer.Input[4],AFC.Prove.ConfigInput.Options) ,MOV(AFC.Util.Buffer.Input[5],AFC.Prove.ConfigInput.RunsPerProveTotal) ,MOV(AFC.Util.Buffer.Input[6],AFC.Prove.ConfigInput.RunsPerProveSelected) ,MOV(AFC.Util.Buffer.Input[7],AFC.Prove.ConfigInput.MaxRunsBeforeAbort) ,MOV(AFC.Util.Buffer.Input[8],AFC.Prove.ConfigInput.ShortPassesPerRun) ,XIC(AFC.Util.Buffer.Input[12].0) OTL(AFC.Prove.Status.ProveAccepted) ,XIO(AFC.Util.Buffer.Input[12].0) OTU(AFC.Prove.Status.ProveAccepted) ,XIC(AFC.Util.Buffer.Input[12].1) OTL(AFC.Prove.Status.MeterFactorApplied) ,XIO(AFC.Util.Buffer.Input[12].1) OTU(AFC.Prove.Status.MeterFactorApplied) ,XIC(AFC.Util.Buffer.Input[12].2) OTL(AFC.Prove.Status.MFAppliedToCurve) ,XIO(AFC.Util.Buffer.Input[12].2) OTU(AFC.Prove.Status.MFAppliedToCurve) ,XIC(AFC.Util.Buffer.Input[12].3) OTL(AFC.Prove.Status.MFAppliedToStreams) ,XIO(AFC.Util.Buffer.Input[12].3) OTU(AFC.Prove.Status.MFAppliedToStreams) ,XIC(AFC.Util.Buffer.Input[12].4) OTL(AFC.Prove.Status.ProveRejectedByCommand) ,XIO(AFC.Util.Buffer.Input[12].4) OTU(AFC.Prove.Status.ProveRejectedByCommand) ,XIC(AFC.Util.Buffer.Input[12].5) OTL(AFC.Prove.Status.ProveRejectedNoRuns) ,XIO(AFC.Util.Buffer.Input[12].5) OTU(AFC.Prove.Status.ProveRejectedNoRuns) ,XIC(AFC.Util.Buffer.Input[12].6) OTL(AFC.Prove.Status.ProveRejectedDivideBy0) ,XIO(AFC.Util.Buffer.Input[12].6) OTU(AFC.Prove.Status.ProveRejectedDivideBy0) ,XIC(AFC.Util.Buffer.Input[12].8) OTL(AFC.Prove.Status.ProveEnabled) ,[XIO(AFC.Util.Buffer.Input[12].8) ,XIC(ProverSignals.2) ,XIC(ProverSignals.3) ,XIC(ProverSignals.14) ] OTU(AFC.Prove.Status.ProveEnabled) ,XIC(AFC.Util.Buffer.Input[12].9) OTL(AFC.Prove.Status.ProvingRunInProgress) ,XIO(AFC.Util.Buffer.Input[12].9) OTU(AFC.Prove.Status.ProvingRunInProgress) ,XIC(AFC.Util.Buffer.Input[12].10) OTL(AFC.Prove.Status.ProvePaused) ,XIO(AFC.Util.Buffer.Input[12].10) OTU(AFC.Prove.Status.ProvePaused) ,XIC(AFC.Util.Buffer.Input[12].11) OTL(AFC.Prove.Status.RunCancelled) ,XIO(AFC.Util.Buffer.Input[12].11) OTU(AFC.Prove.Status.RunCancelled) ,XIC(AFC.Util.Buffer.Input[12].12) OTL(AFC.Prove.Status.RunTimedOut) ,XIO(AFC.Util.Buffer.Input[12].12) OTU(AFC.Prove.Status.RunTimedOut) ,XIC(AFC.Util.Buffer.Input[12].14) OTL(AFC.Prove.Status.ProveRejectedAbort) ,XIO(AFC.Util.Buffer.Input[12].14) OTU(AFC.Prove.Status.ProveRejectedAbort) ,MOV(AFC.Util.Buffer.Input[13],AFC.Prove.ErrorCode) ,MOV(AFC.Util.Buffer.Input[14],AFC.Prove.ProveControlsEcho) ,MOV(AFC.Util.Buffer.Input[15],AFC.Prove.RequestedMeterEcho) ,MOV(AFC.Util.Buffer.Input[17],AFC.Prove.RequestedCurvePointEcho) ,COP(AFC.Util.Buffer.Input[18],AFC.Prove.RunResults.CountAttempted,1) ,COP(AFC.Util.Buffer.Input[19],AFC.Prove.RunResults.CountCompleted,1) ,MOV(AFC.Util.Buffer.Input[20],AFC.Prove.RunResults.CountSelected) ,MOV(AFC.Util.Buffer.Input[21],AFC.Prove.RunResults.RunsSelected) ,COP(AFC.Util.Buffer.Input[22],AFC.Prove.RunResults.NewMeterFactor,1) ,COP(AFC.Util.Buffer.Input[24],AFC.Prove.RunResults.ChangeInMeterFactor,1) ,OTU(AFC.Util.Block.NonInterruptPending.Prover) OTL(AFC.Util.Block.NonInterruptComplete.Prover) ];
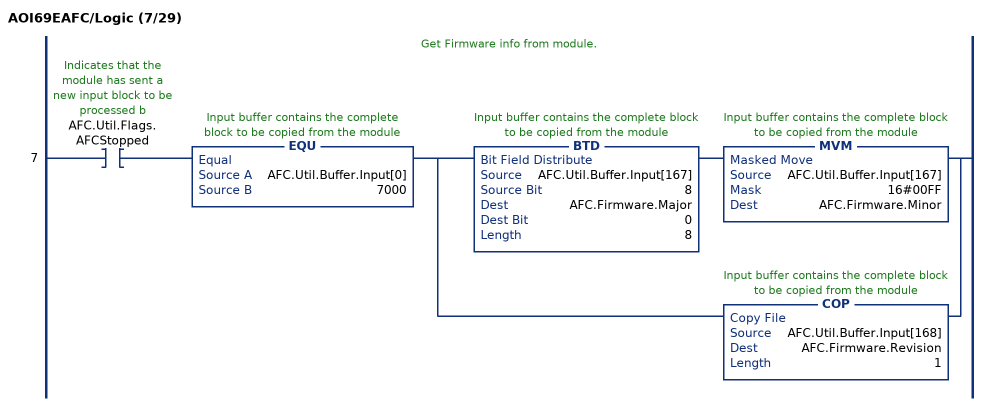
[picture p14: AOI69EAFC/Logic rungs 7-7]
   // Get Firmware info from module.
   7: XIC(AFC.Util.Flags.AFCStopped)EQU(AFC.Util.Buffer.Input[0],7000)[BTD(AFC.Util.Buffer.Input[167],8,AFC.Firmware.Major,0,8) MVM(AFC.Util.Buffer.Input[167],16#00FF,AFC.Firmware.Minor) ,COP(AFC.Util.Buffer.Input[168],AFC.Firmware.Revision,1) ];
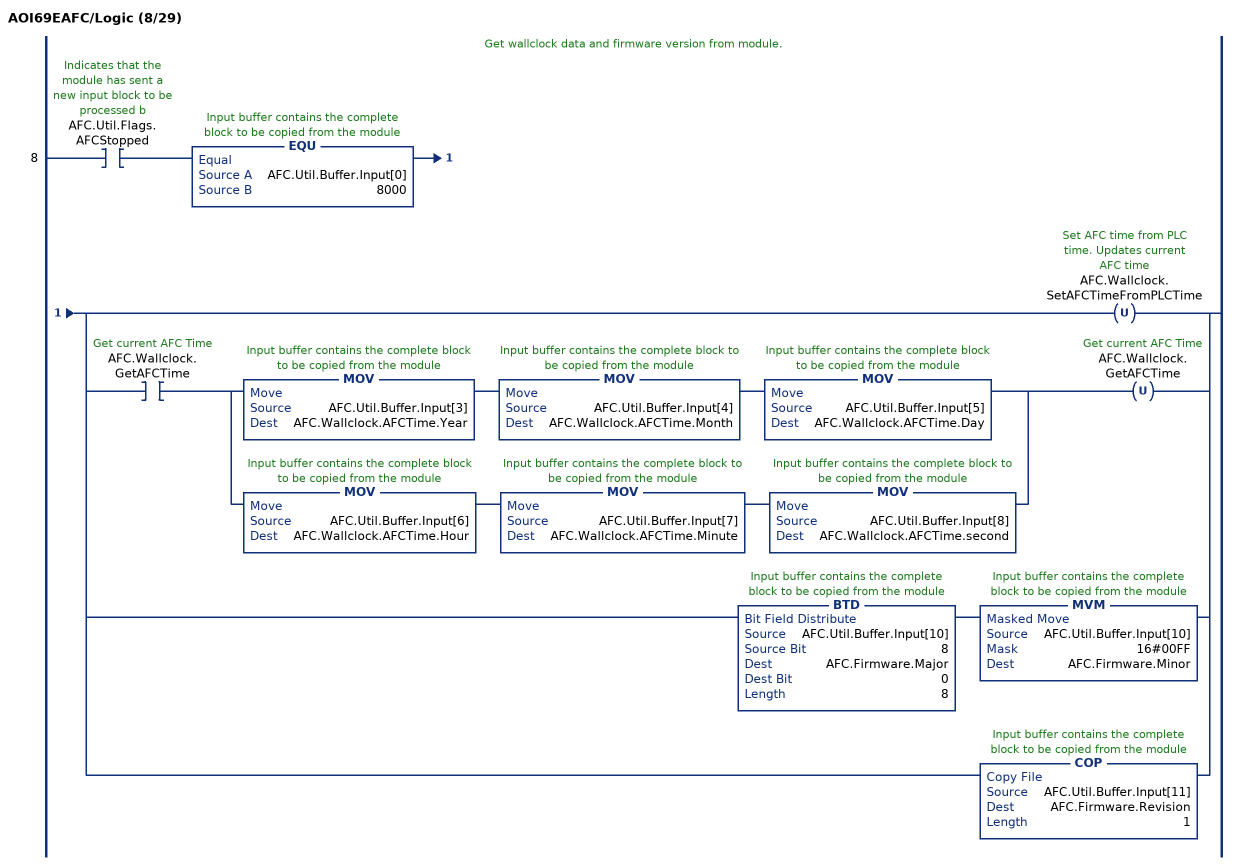
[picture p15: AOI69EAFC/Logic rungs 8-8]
   // Get wallclock data and firmware version from module.
   8: XIC(AFC.Util.Flags.AFCStopped)EQU(AFC.Util.Buffer.Input[0],8000)[OTU(AFC.Wallclock.SetAFCTimeFromPLCTime) ,XIC(AFC.Wallclock.GetAFCTime) [MOV(AFC.Util.Buffer.Input[3],AFC.Wallclock.AFCTime.Year) MOV(AFC.Util.Buffer.Input[4],AFC.Wallclock.AFCTime.Month) MOV(AFC.Util.Buffer.Input[5],AFC.Wallclock.AFCTime.Day) ,MOV(AFC.Util.Buffer.Input[6],AFC.Wallclock.AFCTime.Hour) MOV(AFC.Util.Buffer.Input[7],AFC.Wallclock.AFCTime.Minute) MOV(AFC.Util.Buffer.Input[8],AFC.Wallclock.AFCTime.second) ] OTU(AFC.Wallclock.GetAFCTime) ,[BTD(AFC.Util.Buffer.Input[10],8,AFC.Firmware.Major,0,8) MVM(AFC.Util.Buffer.Input[10],16#00FF,AFC.Firmware.Minor) ,COP(AFC.Util.Buffer.Input[11],AFC.Firmware.Revision,1) ] ];
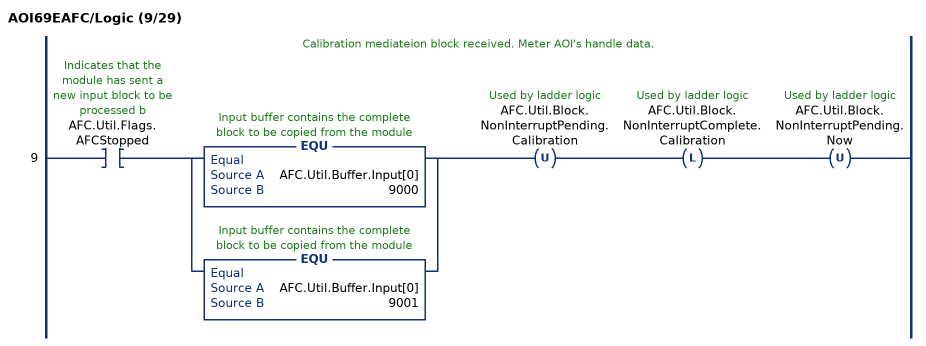
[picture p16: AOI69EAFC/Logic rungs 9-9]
   // Calibration mediateion block received. Meter AOI's handle data.
   9: XIC(AFC.Util.Flags.AFCStopped)[EQU(AFC.Util.Buffer.Input[0],9000) ,EQU(AFC.Util.Buffer.Input[0],9001) ]OTU(AFC.Util.Block.NonInterruptPending.Calibration)OTL(AFC.Util.Block.NonInterruptComplete.Calibration)OTU(AFC.Util.Block.NonInterruptPending.Now);
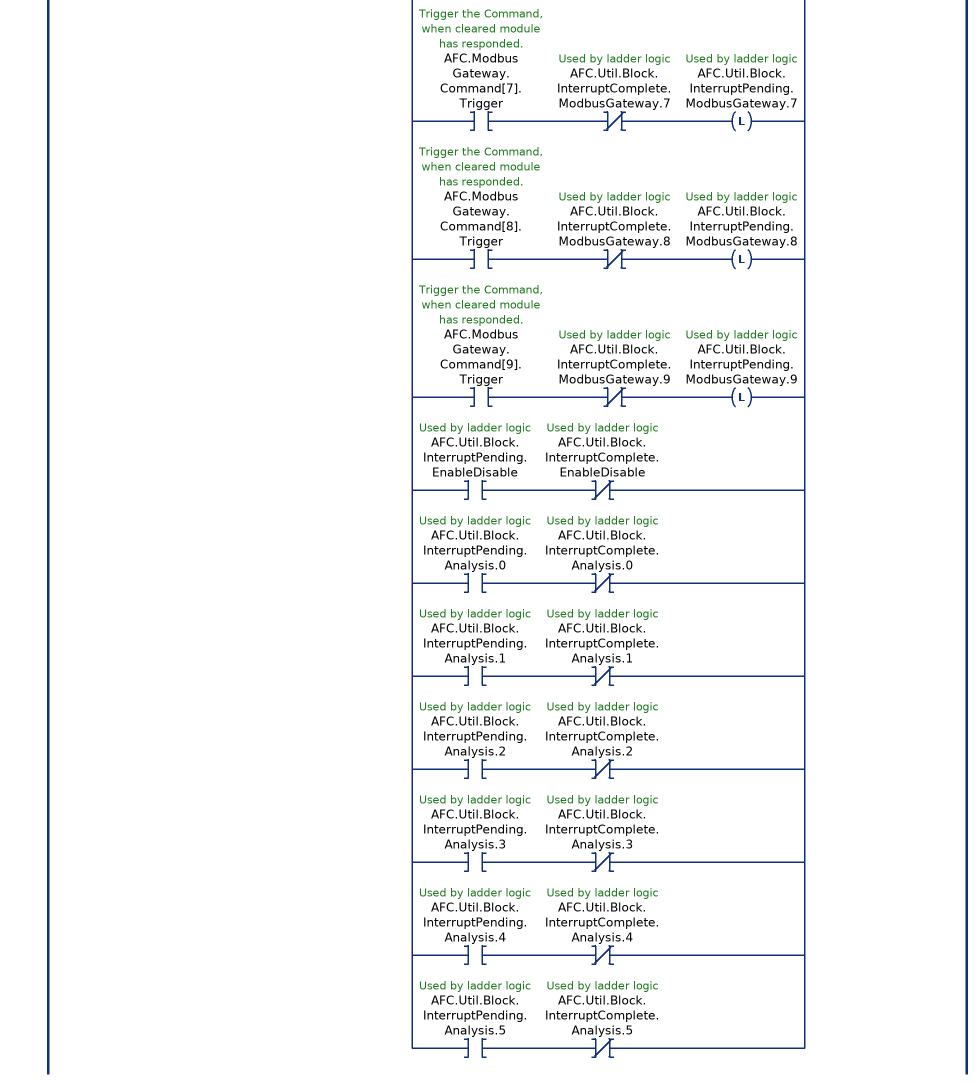
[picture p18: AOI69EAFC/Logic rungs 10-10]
   // Interrupt blocks (3000, 4000 and 7000) are interleaved between Process Input blocks.
   // Check if any interrupt block is pending.
   10: XIC(AFC.Util.Flags.AFCStopped)LIM(1,AFC.Util.Buffer.Input[0],11)[XIC(AFC.ModbusGateway.Command[0].Trigger) XIO(AFC.Util.Block.InterruptComplete.ModbusGateway.0) OTL(AFC.Util.Block.InterruptPending.ModbusGateway.0) ,XIC(AFC.ModbusGateway.Command[1].Trigger) XIO(AFC.Util.Block.InterruptComplete.ModbusGateway.1) OTL(AFC.Util.Block.InterruptPending.ModbusGateway.1) ,XIC(AFC.ModbusGateway.Command[2].Trigger) XIO(AFC.Util.Block.InterruptComplete.ModbusGateway.2) OTL(AFC.Util.Block.InterruptPending.ModbusGateway.2) ,XIC(AFC.ModbusGateway.Command[3].Trigger) XIO(AFC.Util.Block.InterruptComplete.ModbusGateway.3) OTL(AFC.Util.Block.InterruptPending.ModbusGateway.3) ,XIC(AFC.ModbusGateway.Command[4].Trigger) XIO(AFC.Util.Block.InterruptComplete.ModbusGateway.4) OTL(AFC.Util.Block.InterruptPending.ModbusGateway.4) ,XIC(AFC.ModbusGateway.Command[5].Trigger) XIO(AFC.Util.Block.InterruptComplete.ModbusGateway.5) OTL(AFC.Util.Block.InterruptPending.ModbusGateway.5) ,XIC(AFC.ModbusGateway.Command[6].Trigger) XIO(AFC.Util.Block.InterruptComplete.ModbusGateway.6) OTL(AFC.Util.Block.InterruptPending.ModbusGateway.6) ,XIC(AFC.ModbusGateway.Command[7].Trigger) XIO(AFC.Util.Block.InterruptComplete.ModbusGateway.7) OTL(AFC.Util.Block.InterruptPending.ModbusGateway.7) ,XIC(AFC.ModbusGateway.Command[8].Trigger) XIO(AFC.Util.Block.InterruptComplete.ModbusGateway.8) OTL(AFC.Util.Block.InterruptPending.ModbusGateway.8) ,XIC(AFC.ModbusGateway.Command[9].Trigger) XIO(AFC.Util.Block.InterruptComplete.ModbusGateway.9) OTL(AFC.Util.Block.InterruptPending.ModbusGateway.9) ,XIC(AFC.Util.Block.InterruptPending.EnableDisable) XIO(AFC.Util.Block.InterruptComplete.EnableDisable) ,XIC(AFC.Util.Block.InterruptPending.Analysis.0) XIO(AFC.Util.Block.InterruptComplete.Analysis.0) ,XIC(AFC.Util.Block.InterruptPending.Analysis.1) XIO(AFC.Util.Block.InterruptComplete.Analysis.1) ,XIC(AFC.Util.Block.InterruptPending.Analysis.2) XIO(AFC.Util.Block.InterruptComplete.Analysis.2) ,XIC(AFC.Util.Block.InterruptPending.Analysis.3) XIO(AFC.Util.Block.InterruptComplete.Analysis.3) ,XIC(AFC.Util.Block.InterruptPending.Analysis.4) XIO(AFC.Util.Block.InterruptComplete.Analysis.4) ,XIC(AFC.Util.Block.InterruptPending.Analysis.5) XIO(AFC.Util.Block.InterruptComplete.Analysis.5) ]OTL(AFC.Util.Block.InterruptPending.Now);
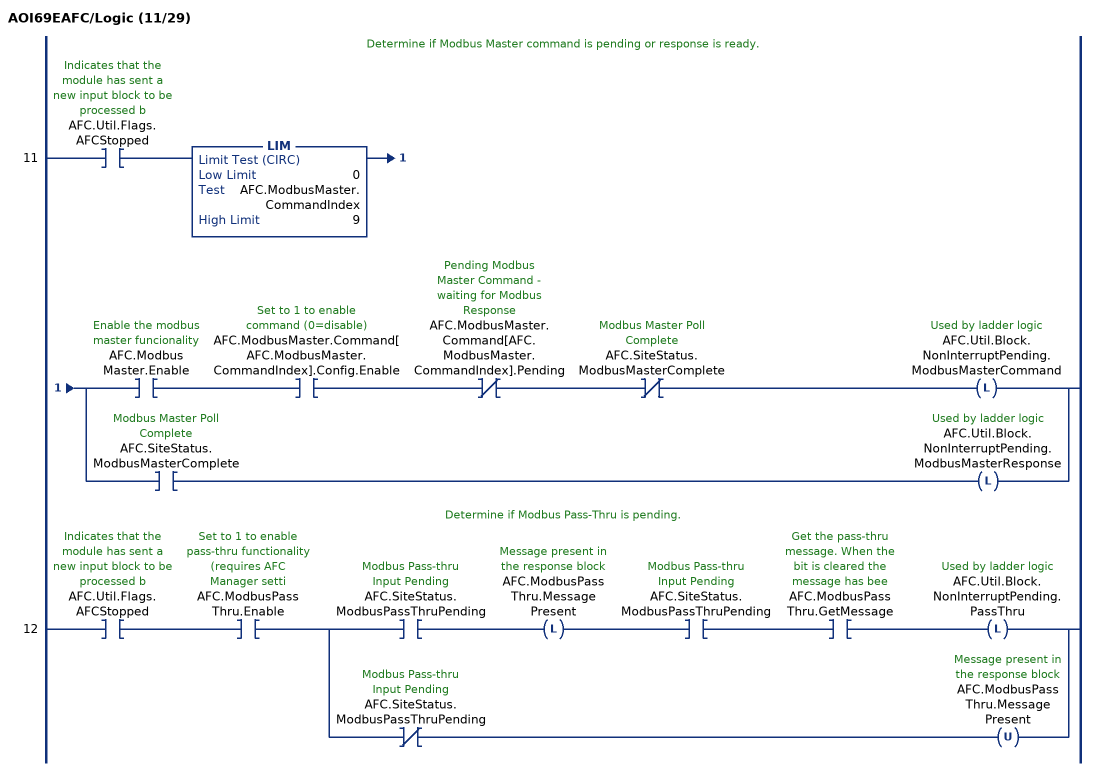
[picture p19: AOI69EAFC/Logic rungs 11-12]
   // Determine if Modbus Master command is pending or response is ready.
   11: XIC(AFC.Util.Flags.AFCStopped)LIM(0,AFC.ModbusMaster.CommandIndex,9)[XIC(AFC.ModbusMaster.Enable) XIC(AFC.ModbusMaster.Command[AFC.ModbusMaster.CommandIndex].Config.Enable) XIO(AFC.ModbusMaster.Command[AFC.ModbusMaster.CommandIndex].Pending) XIO(AFC.SiteStatus.ModbusMasterComplete) OTL(AFC.Util.Block.NonInterruptPending.ModbusMasterCommand) ,XIC(AFC.SiteStatus.ModbusMasterComplete) OTL(AFC.Util.Block.NonInterruptPending.ModbusMasterResponse) ];
   // Determine if Modbus Pass-Thru is pending.
   12: XIC(AFC.Util.Flags.AFCStopped)XIC(AFC.ModbusPassThru.Enable)[XIC(AFC.SiteStatus.ModbusPassThruPending) OTL(AFC.ModbusPassThru.MessagePresent) XIC(AFC.SiteStatus.ModbusPassThruPending) XIC(AFC.ModbusPassThru.GetMessage) OTL(AFC.Util.Block.NonInterruptPending.PassThru) ,XIO(AFC.SiteStatus.ModbusPassThruPending) OTU(AFC.ModbusPassThru.MessagePresent) ];
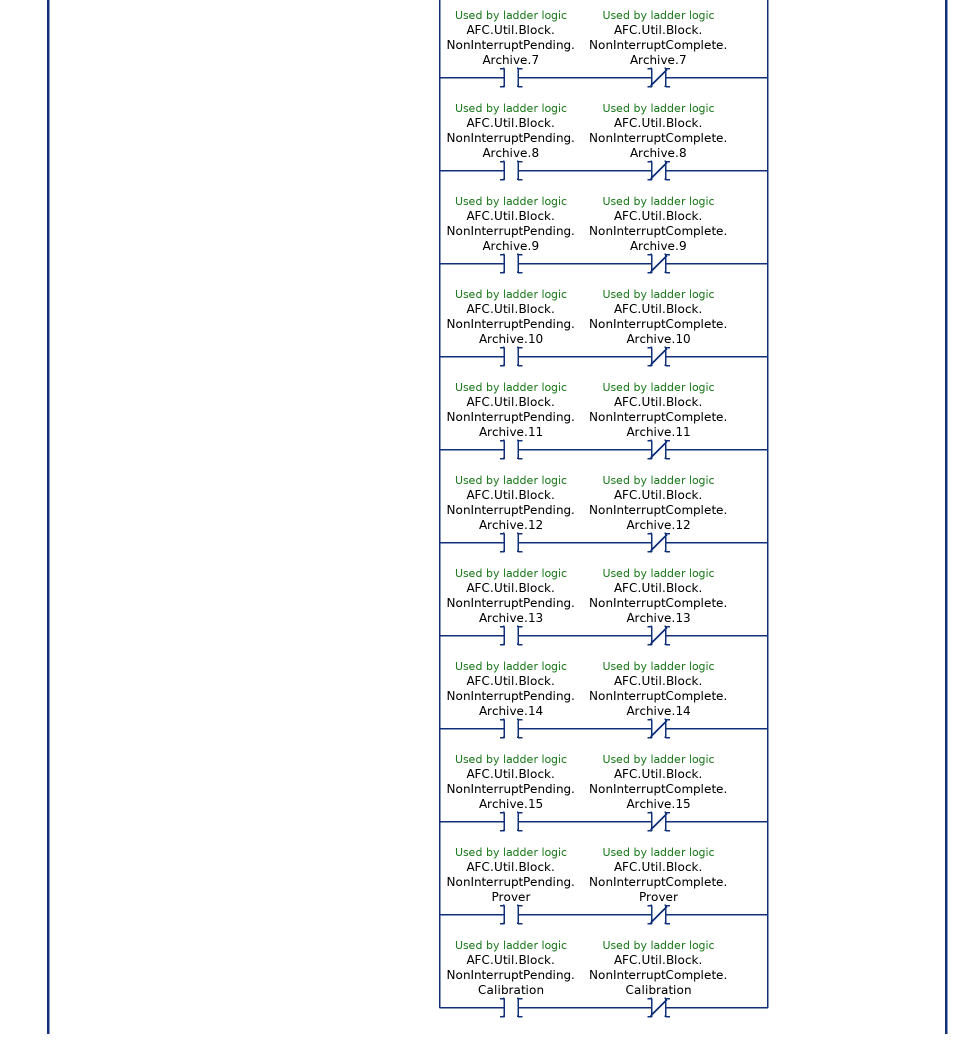
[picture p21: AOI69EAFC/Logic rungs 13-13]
   // Non-Interrupt blocks (1000, 2000 and 5000) occur after Process Input block 12.
   // Check if any non-interrupt block is pending.
   13: XIC(AFC.Util.Flags.AFCStopped)EQU(AFC.Util.Buffer.Input[0],12)[XIC(AFC.Util.Block.NonInterruptPending.ModbusMasterCommand) XIO(AFC.Util.Block.NonInterruptComplete.ModbusMasterCommand) ,XIC(AFC.Util.Block.NonInterruptPending.ModbusMasterResponse) XIO(AFC.Util.Block.NonInterruptComplete.ModbusMasterResponse) ,XIC(AFC.Util.Block.NonInterruptPending.PassThru) XIO(AFC.Util.Block.NonInterruptComplete.PassThru) ,XIC(AFC.Util.Block.NonInterruptPending.Archive.0) XIO(AFC.Util.Block.NonInterruptComplete.Archive.0) ,XIC(AFC.Util.Block.NonInterruptPending.Archive.1) XIO(AFC.Util.Block.NonInterruptComplete.Archive.1) ,XIC(AFC.Util.Block.NonInterruptPending.Archive.2) XIO(AFC.Util.Block.NonInterruptComplete.Archive.2) ,XIC(AFC.Util.Block.NonInterruptPending.Archive.3) XIO(AFC.Util.Block.NonInterruptComplete.Archive.3) ,XIC(AFC.Util.Block.NonInterruptPending.Archive.4) XIO(AFC.Util.Block.NonInterruptComplete.Archive.4) ,XIC(AFC.Util.Block.NonInterruptPending.Archive.5) XIO(AFC.Util.Block.NonInterruptComplete.Archive.5) ,XIC(AFC.Util.Block.NonInterruptPending.Archive.6) XIO(AFC.Util.Block.NonInterruptComplete.Archive.6) ,XIC(AFC.Util.Block.NonInterruptPending.Archive.7) XIO(AFC.Util.Block.NonInterruptComplete.Archive.7) ,XIC(AFC.Util.Block.NonInterruptPending.Archive.8) XIO(AFC.Util.Block.NonInterruptComplete.Archive.8) ,XIC(AFC.Util.Block.NonInterruptPending.Archive.9) XIO(AFC.Util.Block.NonInterruptComplete.Archive.9) ,XIC(AFC.Util.Block.NonInterruptPending.Archive.10) XIO(AFC.Util.Block.NonInterruptComplete.Archive.10) ,XIC(AFC.Util.Block.NonInterruptPending.Archive.11) XIO(AFC.Util.Block.NonInterruptComplete.Archive.11) ,XIC(AFC.Util.Block.NonInterruptPending.Archive.12) XIO(AFC.Util.Block.NonInterruptComplete.Archive.12) ,XIC(AFC.Util.Block.NonInterruptPending.Archive.13) XIO(AFC.Util.Block.NonInterruptComplete.Archive.13) ,XIC(AFC.Util.Block.NonInterruptPending.Archive.14) XIO(AFC.Util.Block.NonInterruptComplete.Archive.14) ,XIC(AFC.Util.Block.NonInterruptPending.Archive.15) XIO(AFC.Util.Block.NonInterruptComplete.Archive.15) ,XIC(AFC.Util.Block.NonInterruptPending.Prover) XIO(AFC.Util.Block.NonInterruptComplete.Prover) ,XIC(AFC.Util.Block.NonInterruptPending.Calibration) XIO(AFC.Util.Block.NonInterruptComplete.Calibration) ]OTL(AFC.Util.Block.NonInterruptPending.Now);
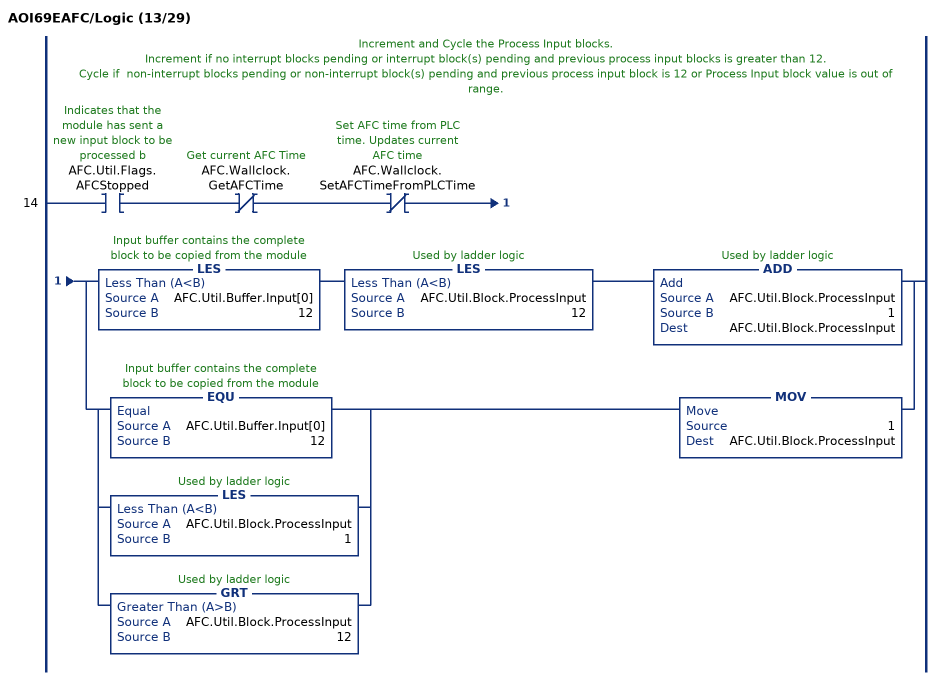
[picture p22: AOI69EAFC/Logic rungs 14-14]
   // Increment and Cycle the Process Input blocks.
   // Increment if no interrupt blocks pending or interrupt block(s) pending and previous process input blocks is greater than 12.
   // Cycle if  non-interrupt blocks pending or non-interrupt block(s) pending and previous process input block is 12 or Process Input block value is out of range.
   14: XIC(AFC.Util.Flags.AFCStopped)XIO(AFC.Wallclock.GetAFCTime)XIO(AFC.Wallclock.SetAFCTimeFromPLCTime)[LES(AFC.Util.Buffer.Input[0],12) LES(AFC.Util.Block.ProcessInput,12) ADD(AFC.Util.Block.ProcessInput,1,AFC.Util.Block.ProcessInput) ,[EQU(AFC.Util.Buffer.Input[0],12) ,LES(AFC.Util.Block.ProcessInput,1) ,GRT(AFC.Util.Block.ProcessInput,12) ] MOV(1,AFC.Util.Block.ProcessInput) ];
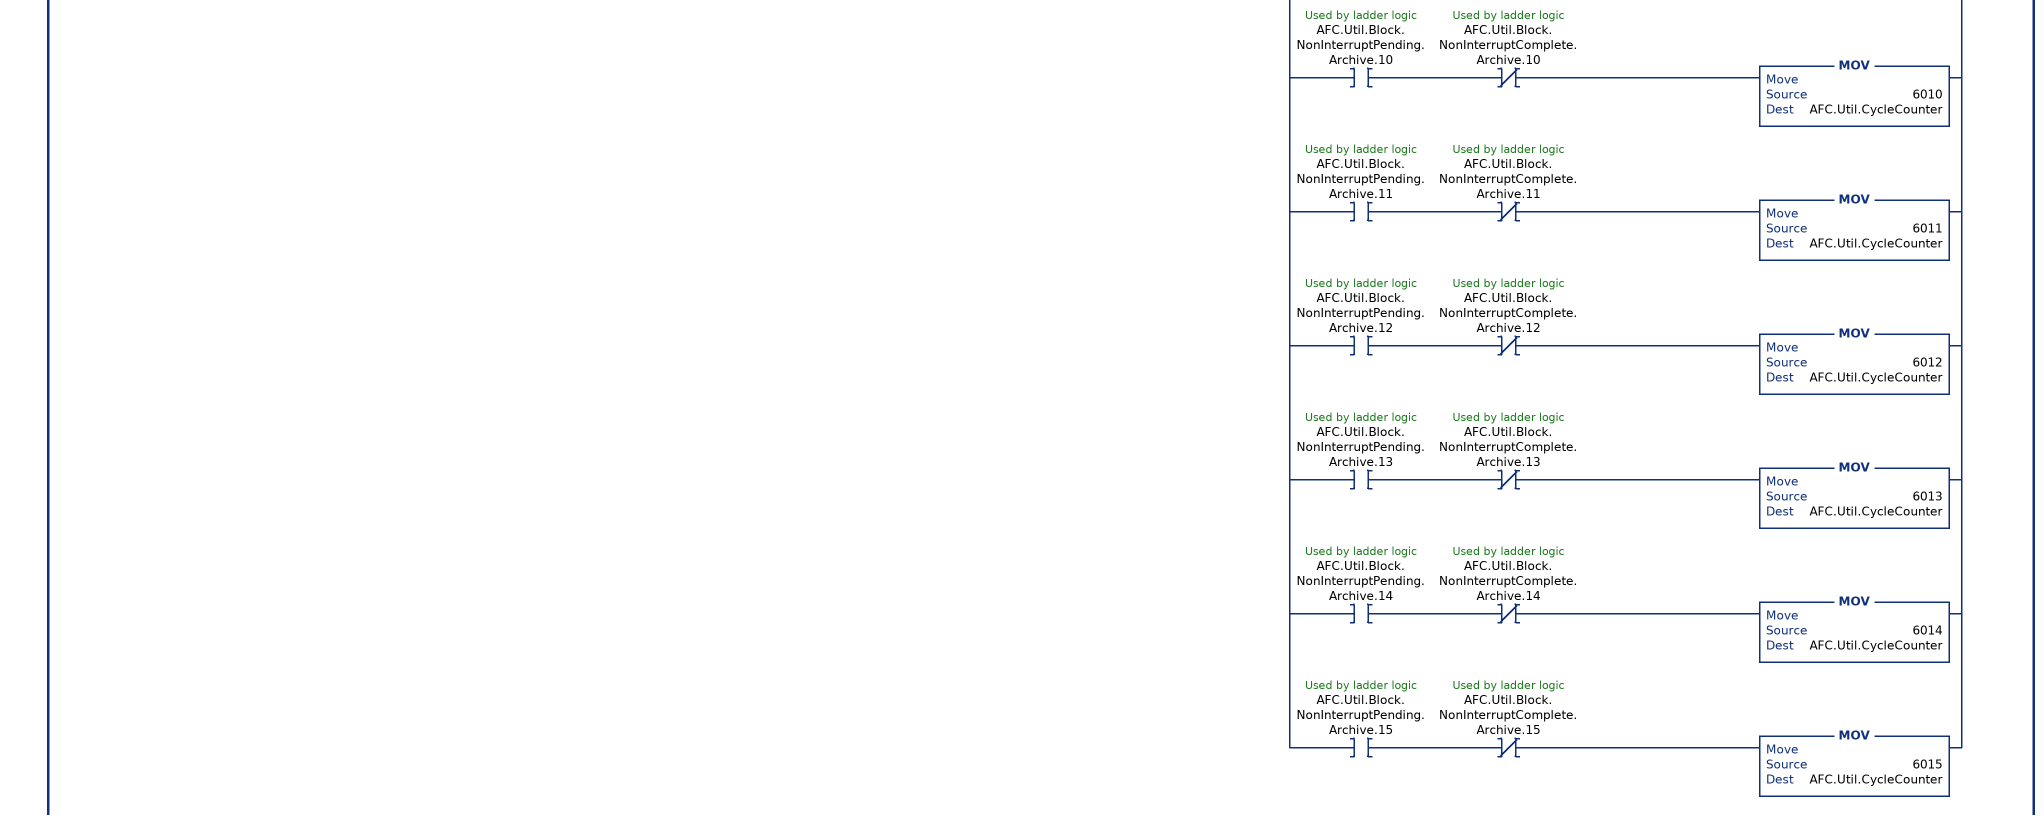
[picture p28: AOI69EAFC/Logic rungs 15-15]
   // Determine the next block to send to module.
   // Send Process Input block if previous block is interrupt or non-interrupt block or either block type is not pending.
   // Send Interrupt block if previous block is Process Input block 1-11 and interrupt block pending.
   // Send Non-interrupt block if previous block is Process Input block 12 and non-interrupt block pending.
   // Note: the block ID has no meaning to the AFC module. The module only requires that the ID changes.
   15: XIC(AFC.Util.Flags.AFCStopped)XIO(AFC.Wallclock.GetAFCTime)XIO(AFC.Wallclock.SetAFCTimeFromPLCTime)[[XIO(AFC.Util.Block.InterruptPending.Now) LIM(1,AFC.Util.Buffer.Input[0],11) ,XIO(AFC.Util.Block.NonInterruptPending.Now) EQU(AFC.Util.Buffer.Input[0],12) ,GRT(AFC.Util.Buffer.Input[0],12) ] MOV(AFC.Util.Block.ProcessInput,AFC.Util.CycleCounter) ,XIC(AFC.Util.Block.InterruptPending.Now) LIM(1,AFC.Util.Buffer.Input[0],11) [[XIC(AFC.Util.Block.InterruptPending.ModbusGateway.0) XIO(AFC.Util.Block.InterruptComplete.ModbusGateway.0) MOV(4000,AFC.Util.CycleCounter) ,XIC(AFC.Util.Block.InterruptPending.ModbusGateway.1) XIO(AFC.Util.Block.InterruptComplete.ModbusGateway.1) MOV(4001,AFC.Util.CycleCounter) ,XIC(AFC.Util.Block.InterruptPending.ModbusGateway.2) XIO(AFC.Util.Block.InterruptComplete.ModbusGateway.2) MOV(4002,AFC.Util.CycleCounter) ,XIC(AFC.Util.Block.InterruptPending.ModbusGateway.3) XIO(AFC.Util.Block.InterruptComplete.ModbusGateway.3) MOV(4003,AFC.Util.CycleCounter) ,XIC(AFC.Util.Block.InterruptPending.ModbusGateway.4) XIO(AFC.Util.Block.InterruptComplete.ModbusGateway.4) MOV(4004,AFC.Util.CycleCounter) ,XIC(AFC.Util.Block.InterruptPending.ModbusGateway.5) XIO(AFC.Util.Block.InterruptComplete.ModbusGateway.5) MOV(4005,AFC.Util.CycleCounter) ,XIC(AFC.Util.Block.InterruptPending.ModbusGateway.6) XIO(AFC.Util.Block.InterruptComplete.ModbusGateway.6) MOV(4006,AFC.Util.CycleCounter) ,XIC(AFC.Util.Block.InterruptPending.ModbusGateway.7) XIO(AFC.Util.Block.InterruptComplete.ModbusGateway.7) MOV(4007,AFC.Util.CycleCounter) ,XIC(AFC.Util.Block.InterruptPending.ModbusGateway.8) XIO(AFC.Util.Block.InterruptComplete.ModbusGateway.8) MOV(4008,AFC.Util.CycleCounter) ,XIC(AFC.Util.Block.InterruptPending.ModbusGateway.9) XIO(AFC.Util.Block.InterruptComplete.ModbusGateway.9) MOV(4009,AFC.Util.CycleCounter) ] ,EQU(AFC.Util.Block.InterruptPending.ModbusGateway,0) XIC(AFC.Util.Block.InterruptPending.EnableDisable) XIO(AFC.Util.Block.InterruptComplete.EnableDisable) MOV(7000,AFC.Util.CycleCounter) ,EQU(AFC.Util.Block.InterruptPending.ModbusGateway,0) XIO(AFC.Util.Block.InterruptPending.EnableDisable) [XIC(AFC.Util.Block.InterruptPending.Analysis.0) XIO(AFC.Util.Block.InterruptComplete.Analysis.0) MOV(3000,AFC.Util.CycleCounter) ,XIC(AFC.Util.Block.InterruptPending.Analysis.1) XIO(AFC.Util.Block.InterruptComplete.Analysis.1) MOV(3001,AFC.Util.CycleCounter) ,XIC(AFC.Util.Block.InterruptPending.Analysis.2) XIO(AFC.Util.Block.InterruptComplete.Analysis.2) MOV(3002,AFC.Util.CycleCounter) ,XIC(AFC.Util.Block.InterruptPending.Analysis.3) XIO(AFC.Util.Block.InterruptComplete.Analysis.3) MOV(3003,AFC.Util.CycleCounter) ,XIC(AFC.Util.Block.InterruptPending.Analysis.4) XIO(AFC.Util.Block.InterruptComplete.Analysis.4) MOV(3004,AFC.Util.CycleCounter) ,XIC(AFC.Util.Block.InterruptPending.Analysis.5) XIO(AFC.Util.Block.InterruptComplete.Analysis.5) MOV(3005,AFC.Util.CycleCounter) ] ] ,XIC(AFC.Util.Block.NonInterruptPending.Now) EQU(AFC.Util.Buffer.Input[0],12) [XIC(AFC.ModbusMaster.Enable) LIM(0,AFC.ModbusMaster.CommandIndex,9) [XIO(AFC.Util.Block.NonInterruptComplete.ModbusMasterCommand) XIC(AFC.ModbusMaster.Command[AFC.ModbusMaster.CommandIndex].Config.Enable) XIO(AFC.SiteStatus.ModbusMasterPending) XIO(AFC.SiteStatus.ModbusMasterComplete) MOV(1000,AFC.Util.CycleCounter) ,XIO(AFC.Util.Block.NonInterruptComplete.ModbusMasterResponse) XIC(AFC.SiteStatus.ModbusMasterComplete) MOV(1001,AFC.Util.CycleCounter) ] ,XIO(AFC.Util.Block.NonInterruptPending.ModbusMasterCommand) XIO(AFC.Util.Block.NonInterruptPending.ModbusMasterResponse) [XIC(AFC.ModbusPassThru.Enable) XIC(AFC.SiteStatus.ModbusPassThruPending) XIC(AFC.ModbusPassThru.GetMessage) MOV(2000,AFC.Util.CycleCounter) ,XIO(AFC.Util.Block.NonInterruptPending.PassThru) [XIC(AFC.Util.Block.NonInterruptPending.Prover) XIO(AFC.Util.Block.NonInterruptComplete.Prover) XIC(AFC.Prove.ProveEnabled) MOV(5000,AFC.Util.CycleCounter) ,XIO(AFC.Util.Block.NonInterruptPending.Prover) [XIC(AFC.SiteStatus.CalibrationRequest) XIO(AFC.Util.Block.NonInterruptComplete.Calibration) [EQU(AFC.Util.Buffer.Calibration[1],0) MOV(9000,AFC.Util.CycleCounter) ,NEQ(AFC.Util.Buffer.Calibration[1],0) MOV(9001,AFC.Util.CycleCounter) ] ,XIO(AFC.Util.Block.NonInterruptPending.Calibration) [XIC(AFC.Util.Block.NonInterruptPending.Archive.0) XIO(AFC.Util.Block.NonInterruptComplete.Archive.0) MOV(6000,AFC.Util.CycleCounter) ,XIC(AFC.Util.Block.NonInterruptPending.Archive.1) XIO(AFC.Util.Block.NonInterruptComplete.Archive.1) MOV(6001,AFC.Util.CycleCounter) ,XIC(AFC.Util.Block.NonInterruptPending.Archive.2) XIO(AFC.Util.Block.NonInterruptComplete.Archive.2) MOV(6002,AFC.Util.CycleCounter) ,XIC(AFC.Util.Block.NonInterruptPending.Archive.3) XIO(AFC.Util.Block.NonInterruptComplete.Archive.3) MOV(6003,AFC.Util.CycleCounter) ,XIC(AFC.Util.Block.NonInterruptPending.Archive.4) XIO(AFC.Util.Block.NonInterruptComplete.Archive.4) MOV(6004,AFC.Util.CycleCounter) ,XIC(AFC.Util.Block.NonInterruptPending.Archive.5) XIO(AFC.Util.Block.NonInterruptComplete.Archive.5) MOV(6005,AFC.Util.CycleCounter) ,XIC(AFC.Util.Block.NonInterruptPending.Archive.6) XIO(AFC.Util.Block.NonInterruptComplete.Archive.6) MOV(6006,AFC.Util.CycleCounter) ,XIC(AFC.Util.Block.NonInterruptPending.Archive.7) XIO(AFC.Util.Block.NonInterruptComplete.Archive.7) MOV(6007,AFC.Util.CycleCounter) ,XIC(AFC.Util.Block.NonInterruptPending.Archive.8) XIO(AFC.Util.Block.NonInterruptComplete.Archive.8) MOV(6008,AFC.Util.CycleCounter) ,XIC(AFC.Util.Block.NonInterruptPending.Archive.9) XIO(AFC.Util.Block.NonInterruptComplete.Archive.9) MOV(6009,AFC.Util.CycleCounter) ,XIC(AFC.Util.Block.NonInterruptPending.Archive.10) XIO(AFC.Util.Block.NonInterruptComplete.Archive.10) MOV(6010,AFC.Util.CycleCounter) ,XIC(AFC.Util.Block.NonInterruptPending.Archive.11) XIO(AFC.Util.Block.NonInterruptComplete.Archive.11) MOV(6011,AFC.Util.CycleCounter) ,XIC(AFC.Util.Block.NonInterruptPending.Archive.12) XIO(AFC.Util.Block.NonInterruptComplete.Archive.12) MOV(6012,AFC.Util.CycleCounter) ,XIC(AFC.Util.Block.NonInterruptPending.Archive.13) XIO(AFC.Util.Block.NonInterruptComplete.Archive.13) MOV(6013,AFC.Util.CycleCounter) ,XIC(AFC.Util.Block.NonInterruptPending.Archive.14) XIO(AFC.Util.Block.NonInterruptComplete.Archive.14) MOV(6014,AFC.Util.CycleCounter) ,XIC(AFC.Util.Block.NonInterruptPending.Archive.15) XIO(AFC.Util.Block.NonInterruptComplete.Archive.15) MOV(6015,AFC.Util.CycleCounter) ] ] ] ] ] ];
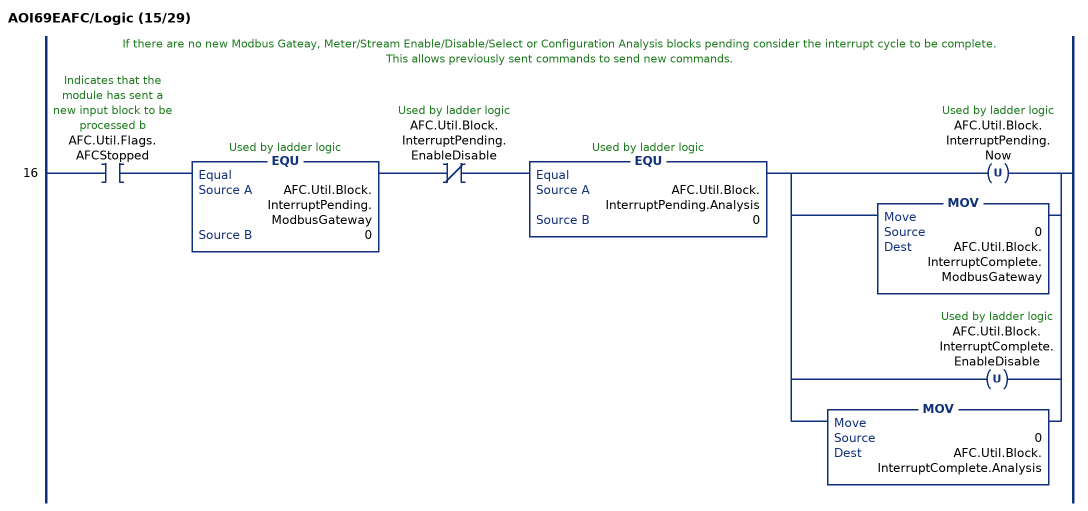
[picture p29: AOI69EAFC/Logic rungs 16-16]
   // If there are no new Modbus Gateay, Meter/Stream Enable/Disable/Select or Configuration Analysis blocks pending consider the interrupt cycle to be complete.
   // This allows previously sent commands to send new commands.
   16: XIC(AFC.Util.Flags.AFCStopped)EQU(AFC.Util.Block.InterruptPending.ModbusGateway,0)XIO(AFC.Util.Block.InterruptPending.EnableDisable)EQU(AFC.Util.Block.InterruptPending.Analysis,0)[OTU(AFC.Util.Block.InterruptPending.Now) ,MOV(0,AFC.Util.Block.InterruptComplete.ModbusGateway) ,OTU(AFC.Util.Block.InterruptComplete.EnableDisable) ,MOV(0,AFC.Util.Block.InterruptComplete.Analysis) ];
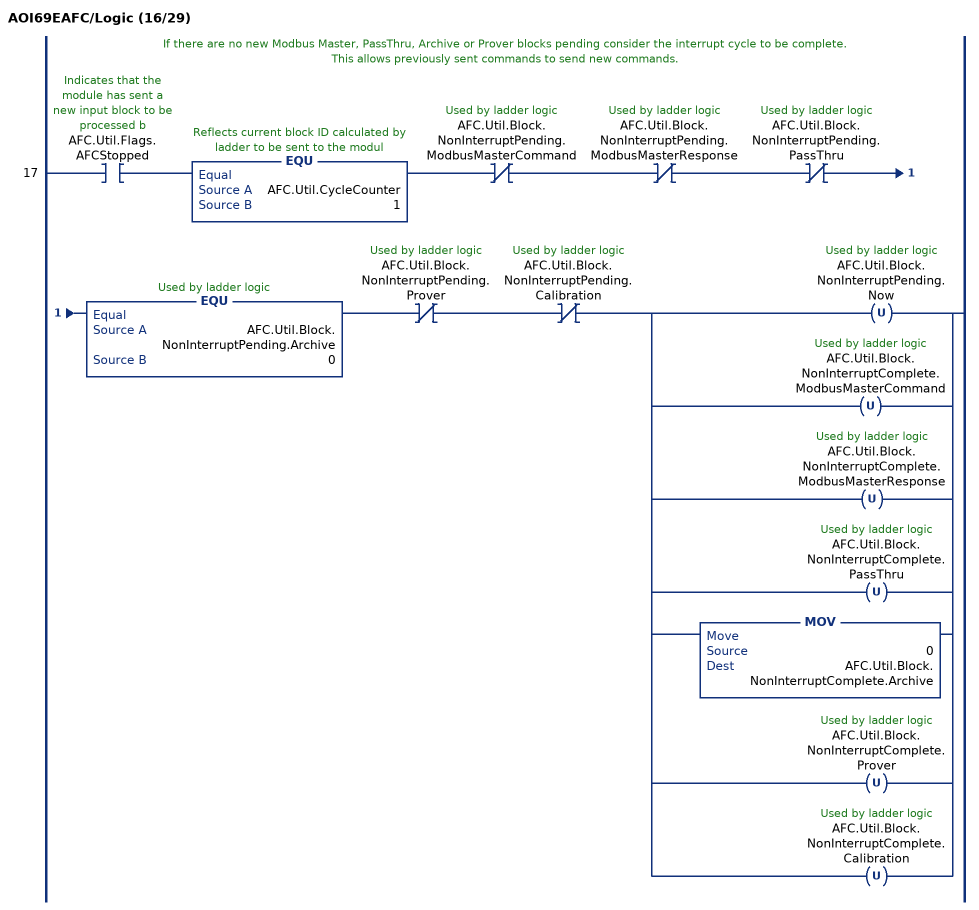
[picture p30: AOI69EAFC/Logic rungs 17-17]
   // If there are no new Modbus Master, PassThru, Archive or Prover blocks pending consider the interrupt cycle to be complete.
   // This allows previously sent commands to send new commands.
   17: XIC(AFC.Util.Flags.AFCStopped)EQU(AFC.Util.CycleCounter,1)XIO(AFC.Util.Block.NonInterruptPending.ModbusMasterCommand)XIO(AFC.Util.Block.NonInterruptPending.ModbusMasterResponse)XIO(AFC.Util.Block.NonInterruptPending.PassThru)EQU(AFC.Util.Block.NonInterruptPending.Archive,0)XIO(AFC.Util.Block.NonInterruptPending.Prover)XIO(AFC.Util.Block.NonInterruptPending.Calibration)[OTU(AFC.Util.Block.NonInterruptPending.Now) ,OTU(AFC.Util.Block.NonInterruptComplete.ModbusMasterCommand) ,OTU(AFC.Util.Block.NonInterruptComplete.ModbusMasterResponse) ,OTU(AFC.Util.Block.NonInterruptComplete.PassThru) ,MOV(0,AFC.Util.Block.NonInterruptComplete.Archive) ,OTU(AFC.Util.Block.NonInterruptComplete.Prover) ,OTU(AFC.Util.Block.NonInterruptComplete.Calibration) ];
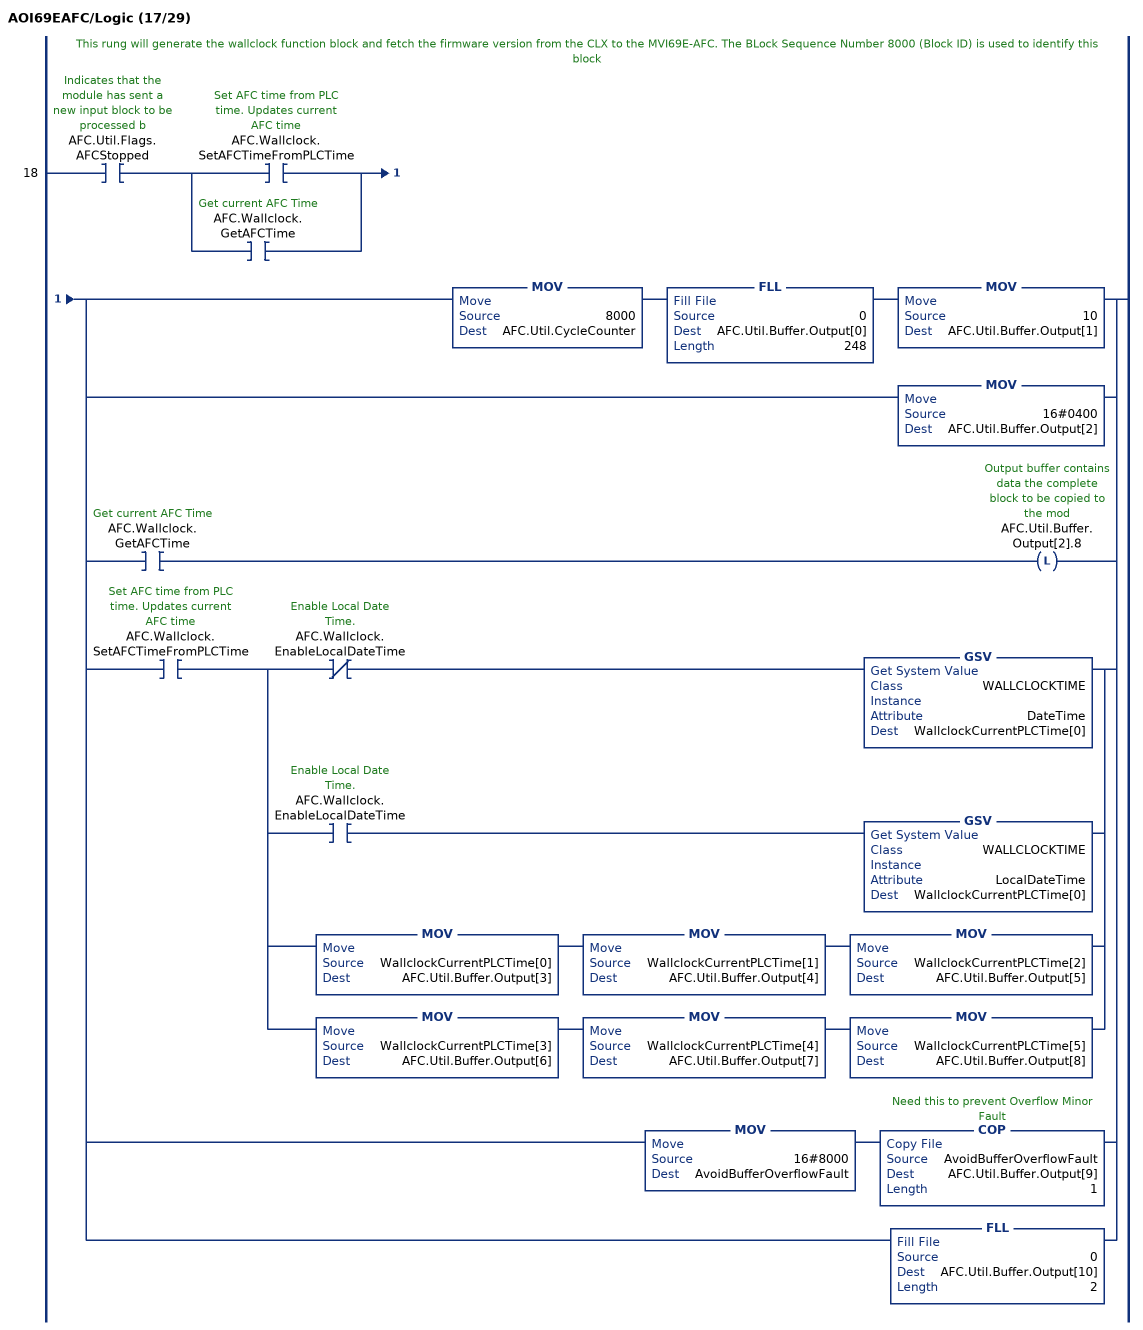
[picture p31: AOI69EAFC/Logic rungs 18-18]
   // This rung will generate the wallclock function block and fetch the firmware version from the CLX to the MVI69E-AFC. The BLock Sequence Number 8000 (Block ID) is used to identify this block
   18: XIC(AFC.Util.Flags.AFCStopped)[XIC(AFC.Wallclock.SetAFCTimeFromPLCTime) ,XIC(AFC.Wallclock.GetAFCTime) ][MOV(8000,AFC.Util.CycleCounter) FLL(0,AFC.Util.Buffer.Output[0],248) MOV(10,AFC.Util.Buffer.Output[1]) ,[MOV(16#0400,AFC.Util.Buffer.Output[2]) ,XIC(AFC.Wallclock.GetAFCTime) OTL(AFC.Util.Buffer.Output[2].8) ] ,XIC(AFC.Wallclock.SetAFCTimeFromPLCTime) [[XIO(AFC.Wallclock.EnableLocalDateTime) GSV(WALLCLOCKTIME,,DateTime,WallclockCurrentPLCTime[0]) ,XIC(AFC.Wallclock.EnableLocalDateTime) GSV(WALLCLOCKTIME,,LocalDateTime,WallclockCurrentPLCTime[0]) ] ,MOV(WallclockCurrentPLCTime[0],AFC.Util.Buffer.Output[3]) MOV(WallclockCurrentPLCTime[1],AFC.Util.Buffer.Output[4]) MOV(WallclockCurrentPLCTime[2],AFC.Util.Buffer.Output[5]) ,MOV(WallclockCurrentPLCTime[3],AFC.Util.Buffer.Output[6]) MOV(WallclockCurrentPLCTime[4],AFC.Util.Buffer.Output[7]) MOV(WallclockCurrentPLCTime[5],AFC.Util.Buffer.Output[8]) ] ,[MOV(16#8000,AvoidBufferOverflowFault) COP(AvoidBufferOverflowFault,AFC.Util.Buffer.Output[9],1) ,FLL(0,AFC.Util.Buffer.Output[10],2) ] ];
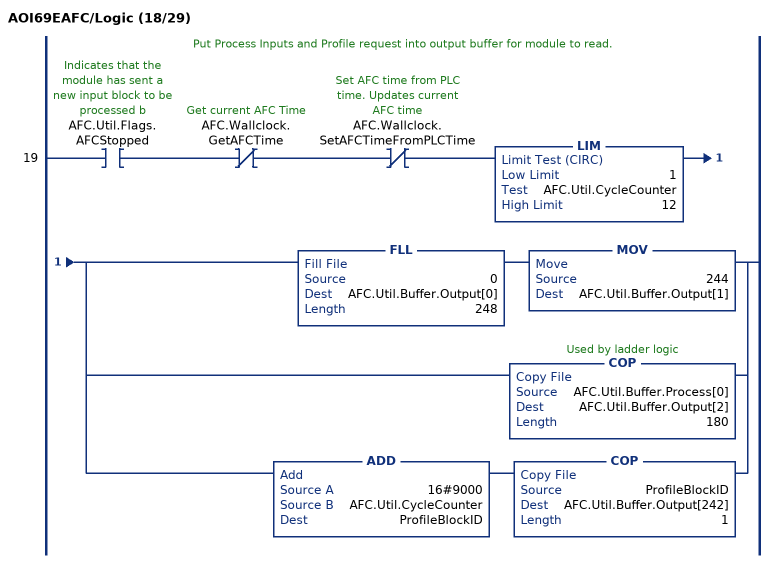
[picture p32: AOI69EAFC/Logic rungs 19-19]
   // Put Process Inputs and Profile request into output buffer for module to read.
   19: XIC(AFC.Util.Flags.AFCStopped)XIO(AFC.Wallclock.GetAFCTime)XIO(AFC.Wallclock.SetAFCTimeFromPLCTime)LIM(1,AFC.Util.CycleCounter,12)[FLL(0,AFC.Util.Buffer.Output[0],248) MOV(244,AFC.Util.Buffer.Output[1]) ,COP(AFC.Util.Buffer.Process[0],AFC.Util.Buffer.Output[2],180) ,ADD(16#9000,AFC.Util.CycleCounter,ProfileBlockID) COP(ProfileBlockID,AFC.Util.Buffer.Output[242],1) ];
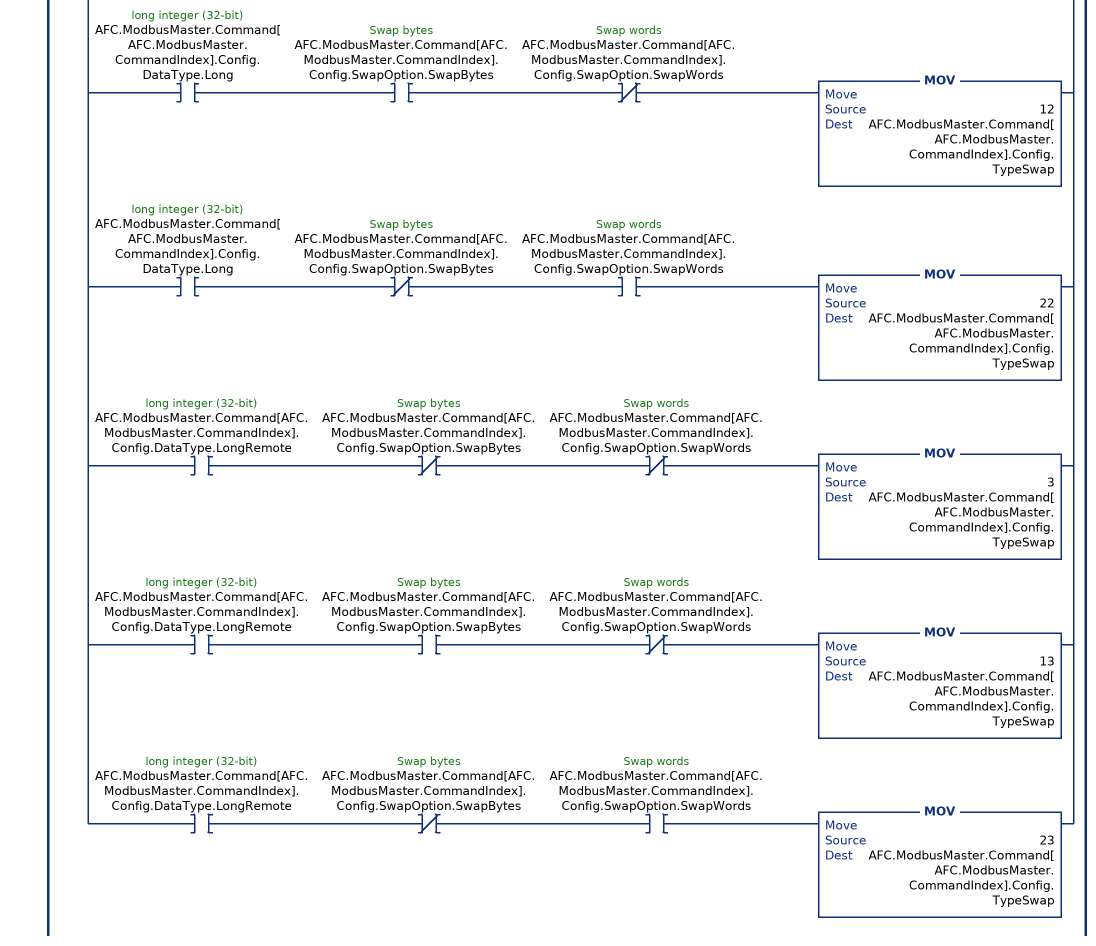
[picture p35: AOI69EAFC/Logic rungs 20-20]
   // Setup Modbus Master command.
   20: XIC(AFC.Util.Flags.AFCStopped)XIO(AFC.Wallclock.GetAFCTime)XIO(AFC.Wallclock.SetAFCTimeFromPLCTime)XIC(AFC.ModbusMaster.Enable)LIM(0,AFC.ModbusMaster.CommandIndex,9)[EQU(AFC.Util.CycleCounter,1000) XIO(AFC.Util.Block.NonInterruptComplete.ModbusMasterCommand) ,EQU(AFC.Util.CycleCounter,1001) XIO(AFC.Util.Block.NonInterruptComplete.ModbusMasterResponse) ][ADD(16#6000,130,ModbusMasterOutput) ,[XIC(AFC.ModbusMaster.Command[AFC.ModbusMaster.CommandIndex].Config.FunctionType) [OTE(ModbusMasterOutput.11) ,OTL(ModbusMasterReadWrite) ] ,XIO(AFC.ModbusMaster.Command[AFC.ModbusMaster.CommandIndex].Config.FunctionType) OTU(ModbusMasterReadWrite) ] ,XIO(AFC.ModbusMaster.Command[AFC.ModbusMaster.CommandIndex].Config.Enable) OTE(ModbusMasterOutput.8) ,XIC(AFC.ModbusMaster.Command[AFC.ModbusMaster.CommandIndex].Config.RegisterBank) OTE(ModbusMasterOutput.10) ,XIC(AFC.ModbusMaster.Command[AFC.ModbusMaster.CommandIndex].Config.DataType.Bit) MOV(0,AFC.ModbusMaster.Command[AFC.ModbusMaster.CommandIndex].Config.TypeSwap) ,XIC(AFC.ModbusMaster.Command[AFC.ModbusMaster.CommandIndex].Config.DataType.Word) XIO(AFC.ModbusMaster.Command[AFC.ModbusMaster.CommandIndex].Config.SwapOption.SwapBytes) MOV(1,AFC.ModbusMaster.Command[AFC.ModbusMaster.CommandIndex].Config.TypeSwap) ,XIC(AFC.ModbusMaster.Command[AFC.ModbusMaster.CommandIndex].Config.DataType.Word) XIC(AFC.ModbusMaster.Command[AFC.ModbusMaster.CommandIndex].Config.SwapOption.SwapBytes) MOV(11,AFC.ModbusMaster.Command[AFC.ModbusMaster.CommandIndex].Config.TypeSwap) ,XIC(AFC.ModbusMaster.Command[AFC.ModbusMaster.CommandIndex].Config.DataType.Long) XIO(AFC.ModbusMaster.Command[AFC.ModbusMaster.CommandIndex].Config.SwapOption.SwapBytes) XIO(AFC.ModbusMaster.Command[AFC.ModbusMaster.CommandIndex].Config.SwapOption.SwapWords) MOV(2,AFC.ModbusMaster.Command[AFC.ModbusMaster.CommandIndex].Config.TypeSwap) ,XIC(AFC.ModbusMaster.Command[AFC.ModbusMaster.CommandIndex].Config.DataType.Long) XIC(AFC.ModbusMaster.Command[AFC.ModbusMaster.CommandIndex].Config.SwapOption.SwapBytes) XIO(AFC.ModbusMaster.Command[AFC.ModbusMaster.CommandIndex].Config.SwapOption.SwapWords) MOV(12,AFC.ModbusMaster.Command[AFC.ModbusMaster.CommandIndex].Config.TypeSwap) ,XIC(AFC.ModbusMaster.Command[AFC.ModbusMaster.CommandIndex].Config.DataType.Long) XIO(AFC.ModbusMaster.Command[AFC.ModbusMaster.CommandIndex].Config.SwapOption.SwapBytes) XIC(AFC.ModbusMaster.Command[AFC.ModbusMaster.CommandIndex].Config.SwapOption.SwapWords) MOV(22,AFC.ModbusMaster.Command[AFC.ModbusMaster.CommandIndex].Config.TypeSwap) ,XIC(AFC.ModbusMaster.Command[AFC.ModbusMaster.CommandIndex].Config.DataType.LongRemote) XIO(AFC.ModbusMaster.Command[AFC.ModbusMaster.CommandIndex].Config.SwapOption.SwapBytes) XIO(AFC.ModbusMaster.Command[AFC.ModbusMaster.CommandIndex].Config.SwapOption.SwapWords) MOV(3,AFC.ModbusMaster.Command[AFC.ModbusMaster.CommandIndex].Config.TypeSwap) ,XIC(AFC.ModbusMaster.Command[AFC.ModbusMaster.CommandIndex].Config.DataType.LongRemote) XIC(AFC.ModbusMaster.Command[AFC.ModbusMaster.CommandIndex].Config.SwapOption.SwapBytes) XIO(AFC.ModbusMaster.Command[AFC.ModbusMaster.CommandIndex].Config.SwapOption.SwapWords) MOV(13,AFC.ModbusMaster.Command[AFC.ModbusMaster.CommandIndex].Config.TypeSwap) ,XIC(AFC.ModbusMaster.Command[AFC.ModbusMaster.CommandIndex].Config.DataType.LongRemote) XIO(AFC.ModbusMaster.Command[AFC.ModbusMaster.CommandIndex].Config.SwapOption.SwapBytes) XIC(AFC.ModbusMaster.Command[AFC.ModbusMaster.CommandIndex].Config.SwapOption.SwapWords) MOV(23,AFC.ModbusMaster.Command[AFC.ModbusMaster.CommandIndex].Config.TypeSwap) ];
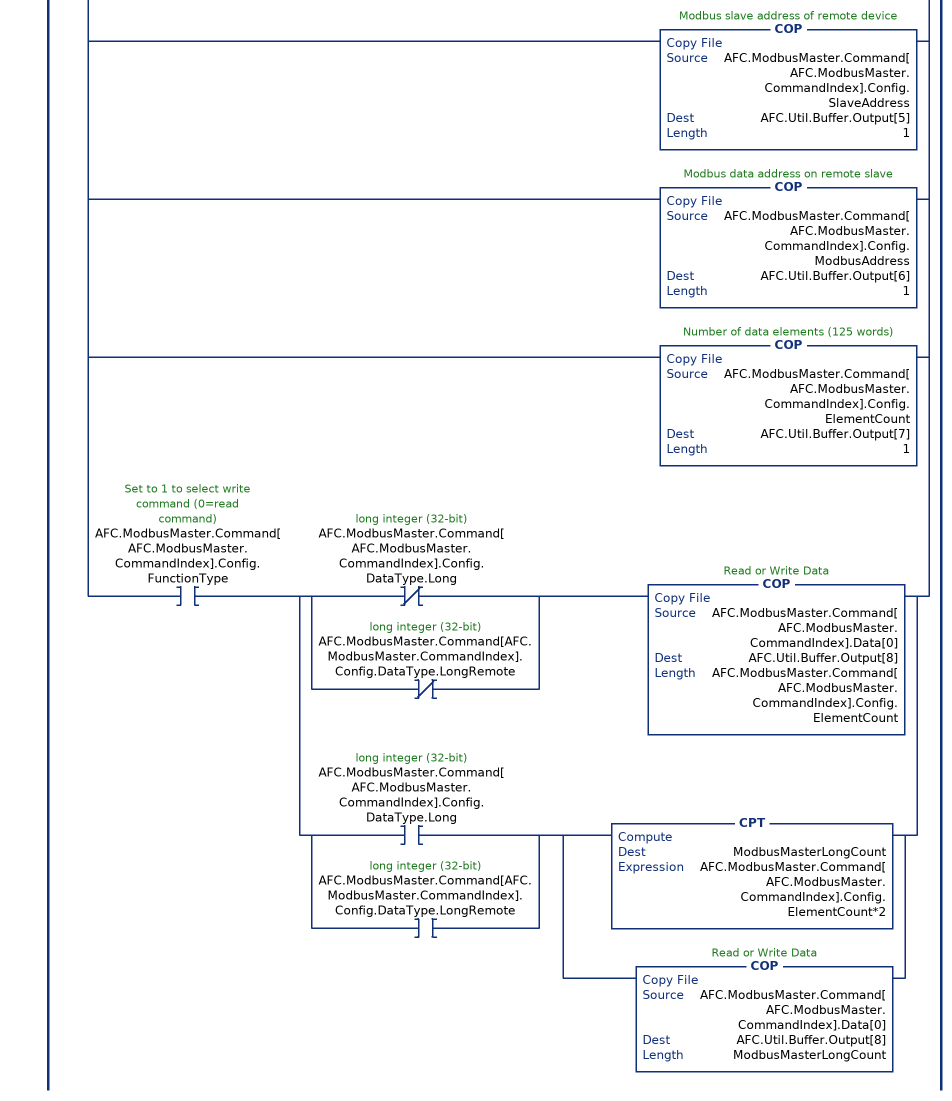
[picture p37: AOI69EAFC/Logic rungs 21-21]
   // Put Modbus Master command into output buffer for module to read.
   21: XIC(AFC.Util.Flags.AFCStopped)XIO(AFC.Wallclock.GetAFCTime)XIO(AFC.Wallclock.SetAFCTimeFromPLCTime)XIC(AFC.ModbusMaster.Enable)LIM(0,AFC.ModbusMaster.CommandIndex,9)[EQU(AFC.Util.CycleCounter,1000) XIO(AFC.Util.Block.NonInterruptComplete.ModbusMasterCommand) ,EQU(AFC.Util.CycleCounter,1001) XIO(AFC.Util.Block.NonInterruptComplete.ModbusMasterResponse) ][MOV(131,AFC.Util.Buffer.Output[1]) ,COP(ModbusMasterOutput,AFC.Util.Buffer.Output[2],1) ,COP(AFC.ModbusMaster.Command[AFC.ModbusMaster.CommandIndex].Config.TransactionID,AFC.Util.Buffer.Output[3],1) ,COP(AFC.ModbusMaster.Command[AFC.ModbusMaster.CommandIndex].Config.TypeSwap,AFC.Util.Buffer.Output[4],1) ,COP(AFC.ModbusMaster.Command[AFC.ModbusMaster.CommandIndex].Config.SlaveAddress,AFC.Util.Buffer.Output[5],1) ,COP(AFC.ModbusMaster.Command[AFC.ModbusMaster.CommandIndex].Config.ModbusAddress,AFC.Util.Buffer.Output[6],1) ,COP(AFC.ModbusMaster.Command[AFC.ModbusMaster.CommandIndex].Config.ElementCount,AFC.Util.Buffer.Output[7],1) ,XIC(AFC.ModbusMaster.Command[AFC.ModbusMaster.CommandIndex].Config.FunctionType) [[XIO(AFC.ModbusMaster.Command[AFC.ModbusMaster.CommandIndex].Config.DataType.Long) ,XIO(AFC.ModbusMaster.Command[AFC.ModbusMaster.CommandIndex].Config.DataType.LongRemote) ] COP(AFC.ModbusMaster.Command[AFC.ModbusMaster.CommandIndex].Data[0],AFC.Util.Buffer.Output[8],AFC.ModbusMaster.Command[AFC.ModbusMaster.CommandIndex].Config.ElementCount) ,[XIC(AFC.ModbusMaster.Command[AFC.ModbusMaster.CommandIndex].Config.DataType.Long) ,XIC(AFC.ModbusMaster.Command[AFC.ModbusMaster.CommandIndex].Config.DataType.LongRemote) ] [CPT(ModbusMasterLongCount,AFC.ModbusMaster.Command[AFC.ModbusMaster.CommandIndex].Config.ElementCount*2) ,COP(AFC.ModbusMaster.Command[AFC.ModbusMaster.CommandIndex].Data[0],AFC.Util.Buffer.Output[8],ModbusMasterLongCount) ] ] ];
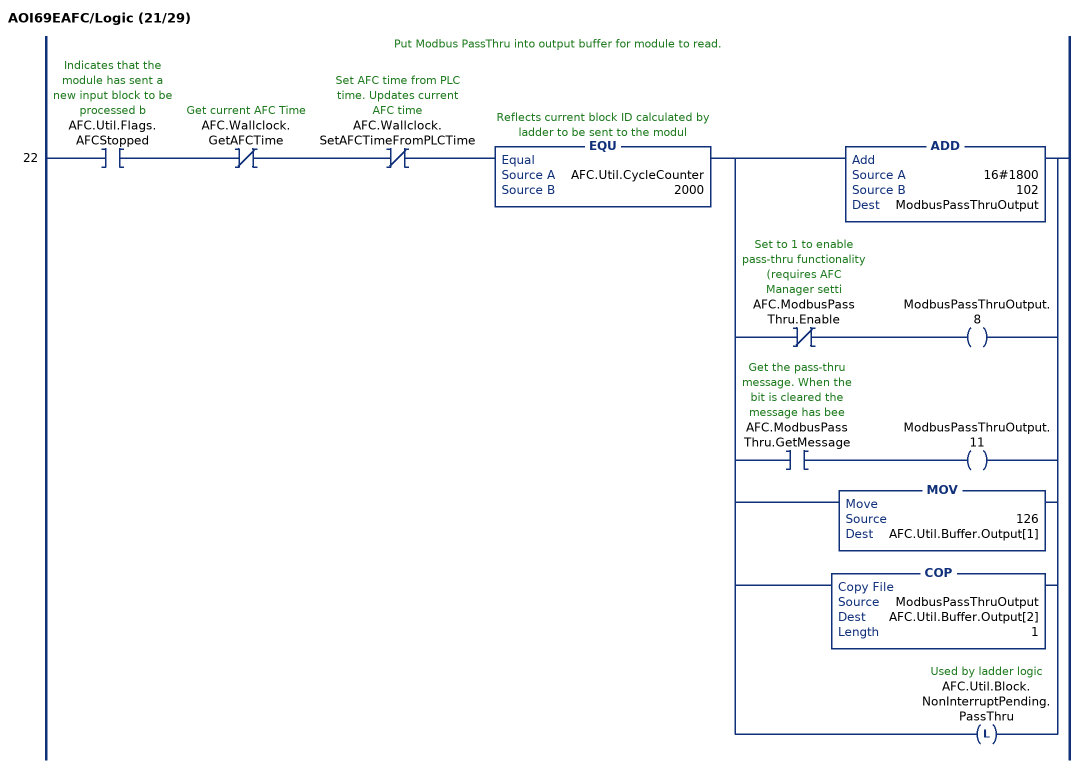
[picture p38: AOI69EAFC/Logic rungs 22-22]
   // Put Modbus PassThru into output buffer for module to read.
   22: XIC(AFC.Util.Flags.AFCStopped)XIO(AFC.Wallclock.GetAFCTime)XIO(AFC.Wallclock.SetAFCTimeFromPLCTime)EQU(AFC.Util.CycleCounter,2000)[ADD(16#1800,102,ModbusPassThruOutput) ,XIO(AFC.ModbusPassThru.Enable) OTE(ModbusPassThruOutput.8) ,XIC(AFC.ModbusPassThru.GetMessage) OTE(ModbusPassThruOutput.11) ,MOV(126,AFC.Util.Buffer.Output[1]) ,COP(ModbusPassThruOutput,AFC.Util.Buffer.Output[2],1) ,OTL(AFC.Util.Block.NonInterruptPending.PassThru) ];
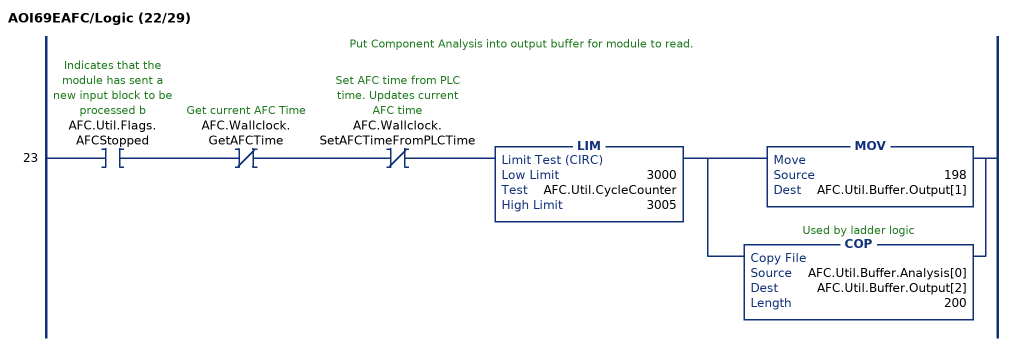
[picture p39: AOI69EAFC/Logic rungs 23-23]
   // Put Component Analysis into output buffer for module to read.
   23: XIC(AFC.Util.Flags.AFCStopped)XIO(AFC.Wallclock.GetAFCTime)XIO(AFC.Wallclock.SetAFCTimeFromPLCTime)LIM(3000,AFC.Util.CycleCounter,3005)[MOV(198,AFC.Util.Buffer.Output[1]) ,COP(AFC.Util.Buffer.Analysis[0],AFC.Util.Buffer.Output[2],200) ];
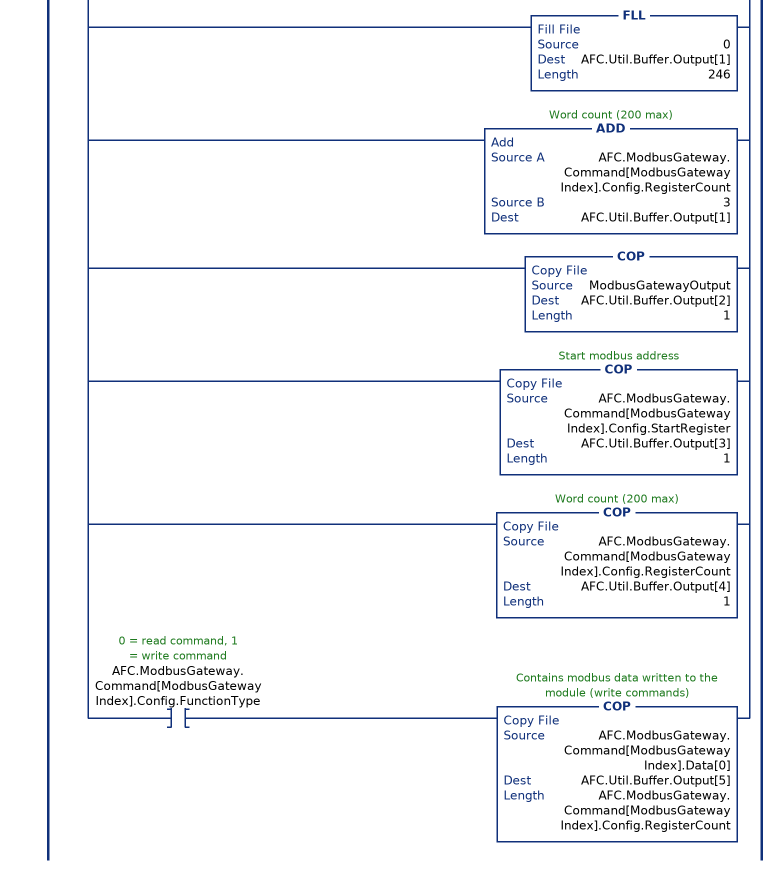
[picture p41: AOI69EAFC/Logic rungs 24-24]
   // Put Modbus Gateway command into output buffer for module to read.
   24: XIC(AFC.Util.Flags.AFCStopped)XIO(AFC.Wallclock.GetAFCTime)XIO(AFC.Wallclock.SetAFCTimeFromPLCTime)LIM(4000,AFC.Util.CycleCounter,4009)[SUB(AFC.Util.CycleCounter,4000,ModbusGatewayIndex) CPT(ModbusGatewayIndexBitPosition,2**ModbusGatewayIndex) ,MOV(16#4000,ModbusGatewayOutput) ,XIO(AFC.ModbusGateway.Command[ModbusGatewayIndex].Config.Enable) OTE(ModbusGatewayOutput.8) ,XIC(AFC.ModbusGateway.Command[ModbusGatewayIndex].Config.SlaveType) OTE(ModbusGatewayOutput.10) ,XIC(AFC.ModbusGateway.Command[ModbusGatewayIndex].Config.RegisterType) OTE(ModbusGatewayOutput.11) ,XIC(AFC.ModbusGateway.Command[ModbusGatewayIndex].Config.FunctionType) OTE(ModbusGatewayOutput.12) ,CPT(ModbusGatewayOutput,ModbusGatewayOutput+AFC.ModbusGateway.Command[ModbusGatewayIndex].Config.RegisterCount+2) ,FLL(0,AFC.Util.Buffer.Output[1],246) ,ADD(AFC.ModbusGateway.Command[ModbusGatewayIndex].Config.RegisterCount,3,AFC.Util.Buffer.Output[1]) ,COP(ModbusGatewayOutput,AFC.Util.Buffer.Output[2],1) ,COP(AFC.ModbusGateway.Command[ModbusGatewayIndex].Config.StartRegister,AFC.Util.Buffer.Output[3],1) ,COP(AFC.ModbusGateway.Command[ModbusGatewayIndex].Config.RegisterCount,AFC.Util.Buffer.Output[4],1) ,XIC(AFC.ModbusGateway.Command[ModbusGatewayIndex].Config.FunctionType) COP(AFC.ModbusGateway.Command[ModbusGatewayIndex].Data[0],AFC.Util.Buffer.Output[5],AFC.ModbusGateway.Command[ModbusGatewayIndex].Config.RegisterCount) ];
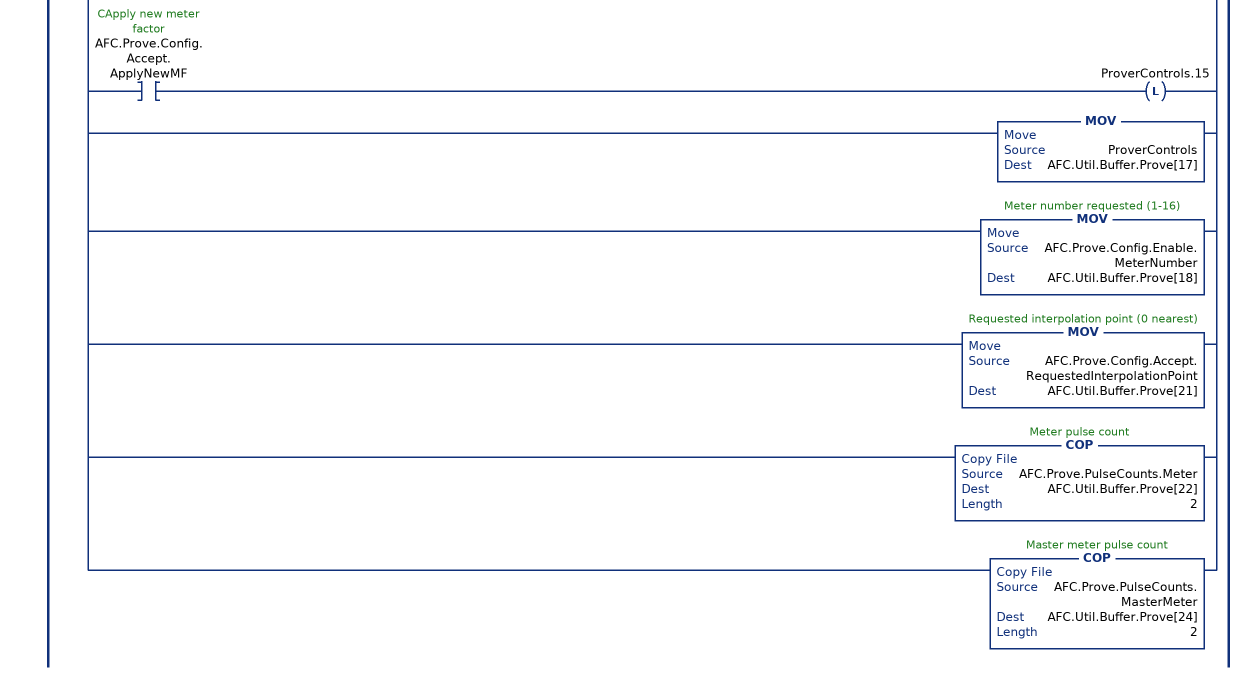
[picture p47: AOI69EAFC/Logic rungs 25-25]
   // The reason to check NEQ outputbuffer[0] 5000 is to guarantee the routine will be updated one time only, so the signals can be cleared correctly once the input block is received
   25: XIC(AFC.Prove.ProveEnabled)[NEQ(AFC.Util.Buffer.Output[0],5000) ,OTL(AFC.Util.Block.NonInterruptPending.Prover) ]EQU(AFC.Util.CycleCounter,5000)[MOV(0,ProverPhase) ,XIC(AFC.Prove.Process.Sequencing.Phase.NotSelected) [OTU(ProverPhase.0) ,OTU(ProverPhase.1) ,OTU(ProverPhase.2) ] ,XIC(AFC.Prove.Process.Sequencing.Phase.Active) [OTL(ProverPhase.0) ,OTU(ProverPhase.1) ,OTU(ProverPhase.2) ] ,XIC(AFC.Prove.Process.Sequencing.Phase.CountingPast1stSwitch) [OTU(ProverPhase.0) ,OTL(ProverPhase.1) ,OTU(ProverPhase.2) ] ,XIC(AFC.Prove.Process.Sequencing.Phase.Past2ndSwitchFwdLeg) [OTL(ProverPhase.0) ,OTL(ProverPhase.1) ,OTU(ProverPhase.2) ] ,XIC(AFC.Prove.Process.Sequencing.Phase.Past1stSwithRetLeg) [OTU(ProverPhase.0) ,OTU(ProverPhase.1) ,OTL(ProverPhase.2) ] ,XIC(AFC.Prove.Process.Sequencing.Phase.RunComplete) [OTL(ProverPhase.0) ,OTU(ProverPhase.1) ,OTL(ProverPhase.2) ] ,NEQ(ProverPhase,1) NEQ(ProverPhase,2) NEQ(ProverPhase,3) NEQ(ProverPhase,4) NEQ(ProverPhase,5) [OTL(AFC.Prove.Process.Sequencing.Phase.NotSelected) ,OTU(AFC.Prove.Process.Sequencing.Phase.Active) ,OTU(AFC.Prove.Process.Sequencing.Phase.CountingPast1stSwitch) ,OTU(AFC.Prove.Process.Sequencing.Phase.Past2ndSwitchFwdLeg) ,OTU(AFC.Prove.Process.Sequencing.Phase.Past1stSwithRetLeg) ,OTU(AFC.Prove.Process.Sequencing.Phase.RunComplete) ,MOV(0,ProverPhase) ] ,XIC(AFC.Prove.Process.Sequencing.BallPositionReady) OTL(ProverPhase.8) ,XIC(AFC.Prove.Process.Sequencing.BallPositionSealed) OTL(ProverPhase.9) ,XIC(AFC.Prove.Process.Sequencing.BallPositionReadyBwdLeg) OTL(ProverPhase.10) ,XIC(AFC.Prove.Process.Sequencing.BallPositionSealedBwdLeg) OTL(ProverPhase.11) ,MOV(16#7C00,AFC.Util.Buffer.Prove[0]) ,MOV(ProverPhase,AFC.Util.Buffer.Prove[1]) ,COP(AFC.Prove.Process.Temperature,AFC.Util.Buffer.Prove[4],2) ,COP(AFC.Prove.Process.OutletTemperature,AFC.Util.Buffer.Prove[6],2) ,COP(AFC.Prove.Process.SwitchBarTemperature,AFC.Util.Buffer.Prove[8],2) ,COP(AFC.Prove.Process.Pressure,AFC.Util.Buffer.Prove[10],2) ,COP(AFC.Prove.Process.OutletPressure,AFC.Util.Buffer.Prove[12],2) ,COP(AFC.Prove.Process.ProverDensity,AFC.Util.Buffer.Prove[14],2) ,MOV(0,ProverSignals) ,XIC(AFC.Prove.Signals.EnableProve) OTL(ProverSignals.1) ,XIC(AFC.Prove.Signals.AcceptProve) OTL(ProverSignals.2) ,XIC(AFC.Prove.Signals.RejectProve) OTL(ProverSignals.3) ,XIC(AFC.Prove.Signals.RunStart) OTL(ProverSignals.4) ,XIC(AFC.Prove.Signals.RunComplete) OTL(ProverSignals.5) ,XIC(AFC.Prove.Signals.RunCancel) OTL(ProverSignals.6) ,XIC(AFC.Prove.Signals.RunDelete) OTL(ProverSignals.7) ,XIC(AFC.Prove.Signals.PassComplete) OTL(ProverSignals.9) ,XIC(AFC.Prove.Signals.PauseProve) OTL(ProverSignals.12) ,XIC(AFC.Prove.Signals.AbortProve) OTL(ProverSignals.14) ,MOV(ProverSignals,AFC.Util.Buffer.Prove[16]) ,[MOV(0,ProverControls) ,XIC(AFC.Prove.Config.Enable.AutoAcceptProve) OTL(ProverControls.0) ,XIC(AFC.Prove.Config.Enable.AutoContinueProve) OTL(ProverControls.1) ,XIC(AFC.Prove.Config.Accept.ApplyMFChangeAllStreams) OTL(ProverControls.13) ,XIC(AFC.Prove.Config.Accept.ApplyMFChangeCurve) OTL(ProverControls.14) ,XIC(AFC.Prove.Config.Accept.ApplyNewMF) OTL(ProverControls.15) ,MOV(ProverControls,AFC.Util.Buffer.Prove[17]) ,MOV(AFC.Prove.Config.Enable.MeterNumber,AFC.Util.Buffer.Prove[18]) ,MOV(AFC.Prove.Config.Accept.RequestedInterpolationPoint,AFC.Util.Buffer.Prove[21]) ] ,[COP(AFC.Prove.PulseCounts.Meter,AFC.Util.Buffer.Prove[22],2) ,COP(AFC.Prove.PulseCounts.MasterMeter,AFC.Util.Buffer.Prove[24],2) ] ];
